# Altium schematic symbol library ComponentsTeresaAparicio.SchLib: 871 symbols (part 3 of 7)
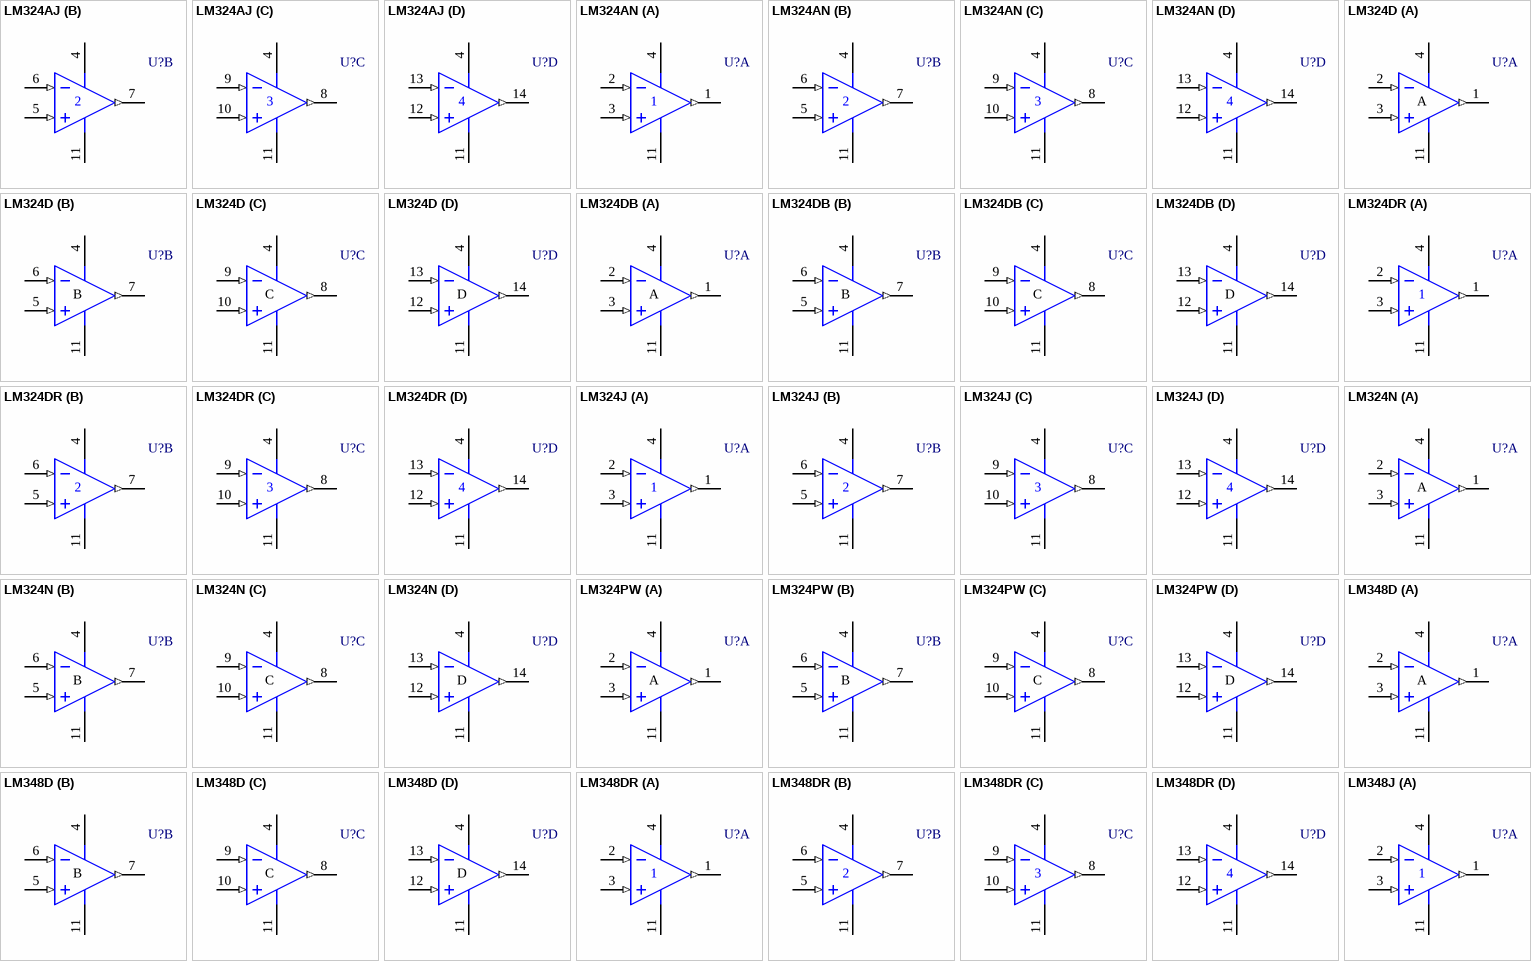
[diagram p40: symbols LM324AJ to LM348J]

## LM348DR
designator U?
Quadruple Operational Amplifier
footprint D014_N (SOIC, 14-Leads, Body 8.7x3.9mm, Pitch 1.27mm, IPC Medium Density)
footprint D014_L (SOIC, 14-Leads, Body 8.7x3.9mm, Pitch 1.27mm, IPC High Density)
footprint D014_M (SOIC, 14-Leads, Body 8.7x3.9mm, Pitch 1.27mm, IPC Low Density)
3D model D014 (14-Pin Small Outline Integrated Circuit 1.27 mm Pitch)
pins on every part: 4 V+ (power), 11 V- (power)
part A pins: 1 OUT (out), 2 IN- (in), 3 IN+ (in)
part B pins: 5 IN+ (in), 6 IN- (in), 7 OUT (out)
part C pins: 8 OUT (out), 9 IN- (in), 10 IN+ (in)
part D pins: 12 IN+ (in), 13 IN- (in), 14 OUT (out)

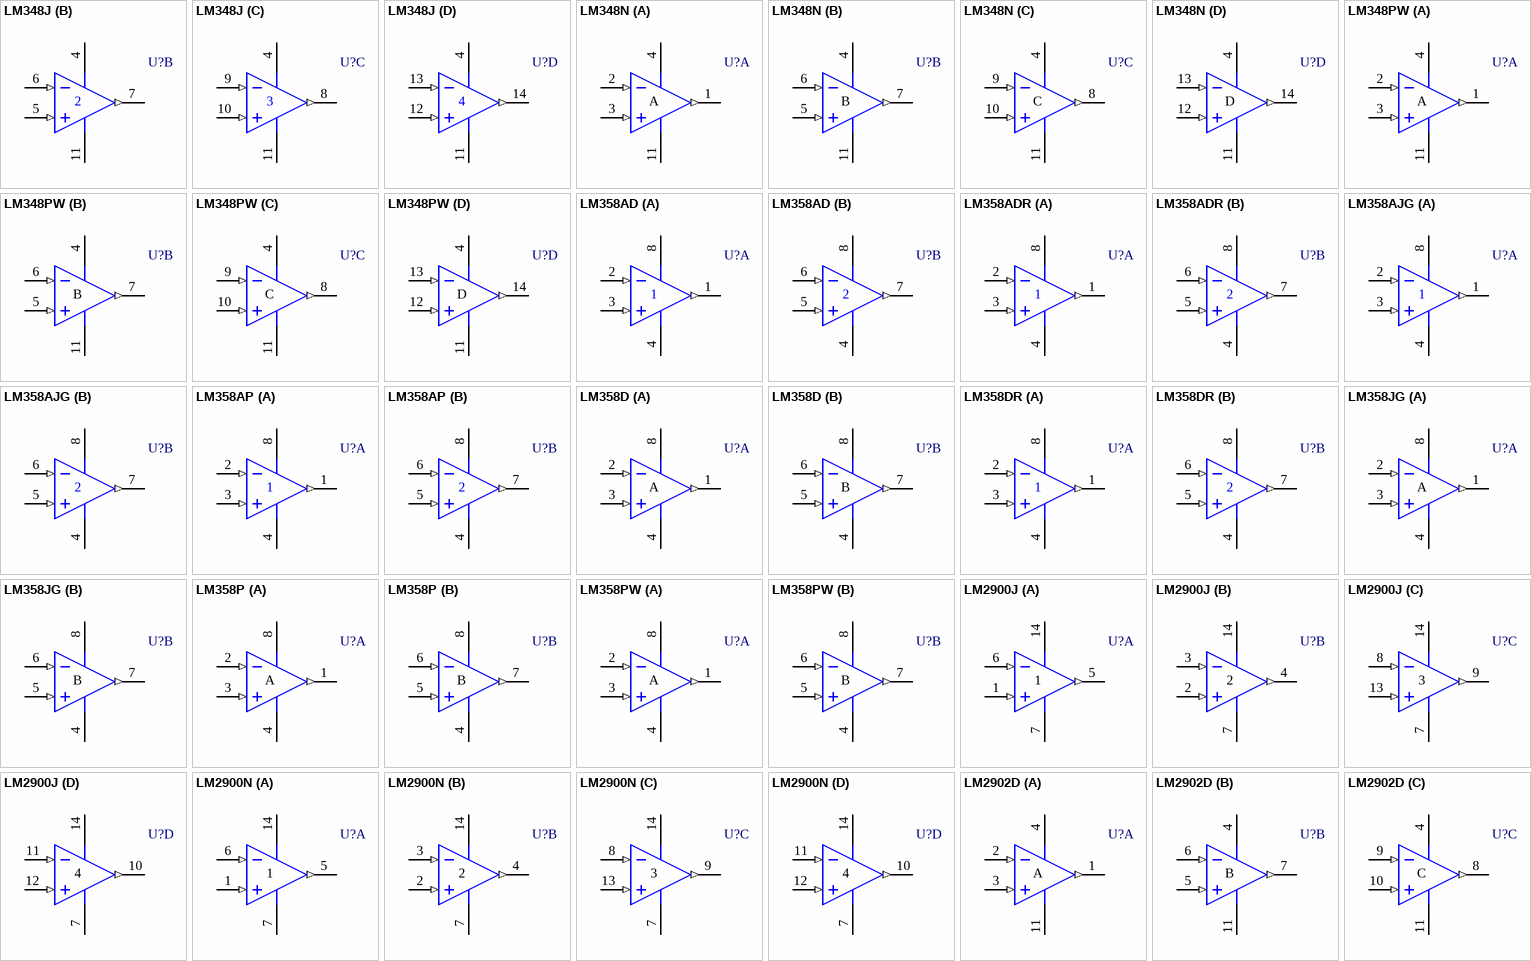
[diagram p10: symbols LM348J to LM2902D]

## LM348J
designator U?
Quadruple Operational Amplifier
footprint J014 (DIP; 14 Leads; Row Spacing 7.62 mm; Pitch 2.54 mm)
3D model J014 (DIP; 14 Leads; Row Spacing 7.62 mm; Pitch 2.54 mm)
pins on every part: 4 V+ (power), 11 V- (power)
part A pins: 1 OUT (out), 2 IN- (in), 3 IN+ (in)
part B pins: 5 IN+ (in), 6 IN- (in), 7 OUT (out)
part C pins: 8 OUT (out), 9 IN- (in), 10 IN+ (in)
part D pins: 12 IN+ (in), 13 IN- (in), 14 OUT (out)

## LM348N
designator U?
Quadruple Operational Amplifier
footprint N014 (DIP; 14 Leads; Row Spacing 7.62 mm; Pitch 2.54 mm)
3D model N014 (DIP; 14 Leads; Row Spacing 7.62 mm; Pitch 2.54 mm)
simulation model LM348 (SUBCKT)
pins on every part: 4 V+ (power), 11 V- (power)
part A pins: 1 OUT (out), 2 IN- (in), 3 IN+ (in)
part B pins: 5 IN+ (in), 6 IN- (in), 7 OUT (out)
part C pins: 8 OUT (out), 9 IN- (in), 10 IN+ (in)
part D pins: 12 IN+ (in), 13 IN- (in), 14 OUT (out)

## LM348PW
designator U?
Quadruple Operational Amplifier
footprint PW014_N (TSOP, 14-Leads, Body 5x4.4mm, Pitch 0.65mm, IPC Medium Density)
footprint PW014_L (TSOP, 14-Leads, Body 5x4.4mm, Pitch 0.65mm, IPC High Density)
footprint PW014_M (TSOP, 14-Leads, Body 5x4.4mm, Pitch 0.65mm, IPC Low Density)
3D model PW014 (14-Pin Thin Small Outline Package 0.65 mm Pitch)
simulation model LM348 (SUBCKT)
pins on every part: 4 V+ (power), 11 V- (power)
part A pins: 1 OUT (out), 2 IN- (in), 3 IN+ (in)
part B pins: 5 IN+ (in), 6 IN- (in), 7 OUT (out)
part C pins: 8 OUT (out), 9 IN- (in), 10 IN+ (in)
part D pins: 12 IN+ (in), 13 IN- (in), 14 OUT (out)

## LM358AD
designator U?
Dual Operational Amplifier
footprint D008_L (SOIC, 8-Leads, Body 4.9x3.9mm, Pitch 1.27mm, IPC High Density)
footprint D008_M (SOIC, 8-Leads, Body 4.9x3.9mm, Pitch 1.27mm, IPC Low Density)
footprint D008_M (SOIC, 8-Leads, Body 4.9x3.9mm, Pitch 1.27mm, IPC Low Density)
3D model D008 (8-Pin Small Outline Integrated Circuit 1.27 mm Pitch)
pins on every part: 4 V- (power), 8 V+ (power)
part A pins: 1 OUT (out), 2 IN- (in), 3 IN+ (in)
part B pins: 5 IN+ (in), 6 IN- (in), 7 OUT (out)

## LM358ADR
designator U?
Dual Operational Amplifier
footprint D008_L (SOIC, 8-Leads, Body 4.9x3.9mm, Pitch 1.27mm, IPC High Density)
footprint D008_M (SOIC, 8-Leads, Body 4.9x3.9mm, Pitch 1.27mm, IPC Low Density)
footprint D008_M (SOIC, 8-Leads, Body 4.9x3.9mm, Pitch 1.27mm, IPC Low Density)
3D model D008 (8-Pin Small Outline Integrated Circuit 1.27 mm Pitch)
pins on every part: 4 V- (power), 8 V+ (power)
part A pins: 1 OUT (out), 2 IN- (in), 3 IN+ (in)
part B pins: 5 IN+ (in), 6 IN- (in), 7 OUT (out)

## LM358AJG
designator U?
Dual Operational Amplifier
footprint JG008 (DIP; 8 Leads; Row Spacing 7.62 mm; Pitch 2.54 mm)
3D model JG008 (DIP; 8 Leads; Row Spacing 7.62 mm; Pitch 2.54 mm)
pins on every part: 4 V- (power), 8 V+ (power)
part A pins: 1 OUT (out), 2 IN- (in), 3 IN+ (in)
part B pins: 5 IN+ (in), 6 IN- (in), 7 OUT (out)

## LM358AP
designator U?
Dual Operational Amplifier
footprint P008 (DIP; 8 Leads; Row Spacing 7.62 mm; Pitch 2.54 mm)
3D model P008 (PCB3D Model)
pins on every part: 4 V- (power), 8 V+ (power)
part A pins: 1 OUT (out), 2 IN- (in), 3 IN+ (in)
part B pins: 5 IN+ (in), 6 IN- (in), 7 OUT (out)

## LM358D
designator U?
Dual Operational Amplifier
footprint D008_L (SOIC, 8-Leads, Body 4.9x3.9mm, Pitch 1.27mm, IPC High Density)
footprint D008_M (SOIC, 8-Leads, Body 4.9x3.9mm, Pitch 1.27mm, IPC Low Density)
footprint D008_M (SOIC, 8-Leads, Body 4.9x3.9mm, Pitch 1.27mm, IPC Low Density)
3D model D008 (8-Pin Small Outline Integrated Circuit 1.27 mm Pitch)
simulation model LM358 (SUBCKT)
pins on every part: 4 V- (power), 8 V+ (power)
part A pins: 1 OUT (out), 2 IN- (in), 3 IN+ (in)
part B pins: 5 IN+ (in), 6 IN- (in), 7 OUT (out)

## LM358DR
designator U?
Dual Operational Amplifier
footprint D008_L (SOIC, 8-Leads, Body 4.9x3.9mm, Pitch 1.27mm, IPC High Density)
footprint D008_M (SOIC, 8-Leads, Body 4.9x3.9mm, Pitch 1.27mm, IPC Low Density)
footprint D008_M (SOIC, 8-Leads, Body 4.9x3.9mm, Pitch 1.27mm, IPC Low Density)
3D model D008 (8-Pin Small Outline Integrated Circuit 1.27 mm Pitch)
pins on every part: 4 V- (power), 8 V+ (power)
part A pins: 1 OUT (out), 2 IN- (in), 3 IN+ (in)
part B pins: 5 IN+ (in), 6 IN- (in), 7 OUT (out)

## LM358JG
designator U?
Dual Operational Amplifier
footprint JG008 (DIP; 8 Leads; Row Spacing 7.62 mm; Pitch 2.54 mm)
3D model JG008 (DIP; 8 Leads; Row Spacing 7.62 mm; Pitch 2.54 mm)
simulation model LM358 (SUBCKT)
pins on every part: 4 V- (power), 8 V+ (power)
part A pins: 1 OUT (out), 2 IN- (in), 3 IN+ (in)
part B pins: 5 IN+ (in), 6 IN- (in), 7 OUT (out)

## LM358P
designator U?
Dual Operational Amplifier
footprint P008 (DIP; 8 Leads; Row Spacing 7.62 mm; Pitch 2.54 mm)
3D model P008 (DIP; 8 Leads; Row Spacing 7.62 mm; Pitch 2.54 mm)
simulation model LM358 (SUBCKT)
pins on every part: 4 V- (power), 8 V+ (power)
part A pins: 1 OUT (out), 2 IN- (in), 3 IN+ (in)
part B pins: 5 IN+ (in), 6 IN- (in), 7 OUT (out)

## LM358PW
designator U?
Dual Operational Amplifier
footprint PW008_N (SOP, 8-Leads, Body 3x4.4mm, Pitch 0.65mm, IPC Medium Density)
footprint PW008_L (SOP, 8-Leads, Body 3x4.4mm, Pitch 0.65mm, IPC High Density)
footprint PW008_M (SOP, 8-Leads, Body 3x4.4mm, Pitch 0.65mm, IPC Low Density)
3D model PW008 (8-Pin Small Outline Package 0.65 mm Pitch)
simulation model LM358 (SUBCKT)
pins on every part: 4 V- (power), 8 V+ (power)
part A pins: 1 OUT (out), 2 IN- (in), 3 IN+ (in)
part B pins: 5 IN+ (in), 6 IN- (in), 7 OUT (out)

## LM2900J
designator U?
Quadruple Operational Amplifier
footprint J014 (DIP; 14 Leads; Row Spacing 7.62 mm; Pitch 2.54 mm)
3D model J014 (DIP; 14 Leads; Row Spacing 7.62 mm; Pitch 2.54 mm)
pins on every part: 7 GND (power), 14 V+ (power)
part A pins: 1 IN+ (in), 5 OUT (out), 6 IN- (in)
part B pins: 2 IN+ (in), 3 IN- (in), 4 OUT (out)
part C pins: 8 IN- (in), 9 OUT (out), 13 IN+ (in)
part D pins: 10 OUT (out), 11 IN- (in), 12 IN+ (in)

## LM2900N
designator U?
Quadruple Operational Amplifier
footprint N014 (DIP; 14 Leads; Row Spacing 7.62 mm; Pitch 2.54 mm)
3D model N014 (DIP; 14 Leads; Row Spacing 7.62 mm; Pitch 2.54 mm)
pins on every part: 7 GND (power), 14 V+ (power)
part A pins: 1 IN+ (in), 5 OUT (out), 6 IN- (in)
part B pins: 2 IN+ (in), 3 IN- (in), 4 OUT (out)
part C pins: 8 IN- (in), 9 OUT (out), 13 IN+ (in)
part D pins: 10 OUT (out), 11 IN- (in), 12 IN+ (in)

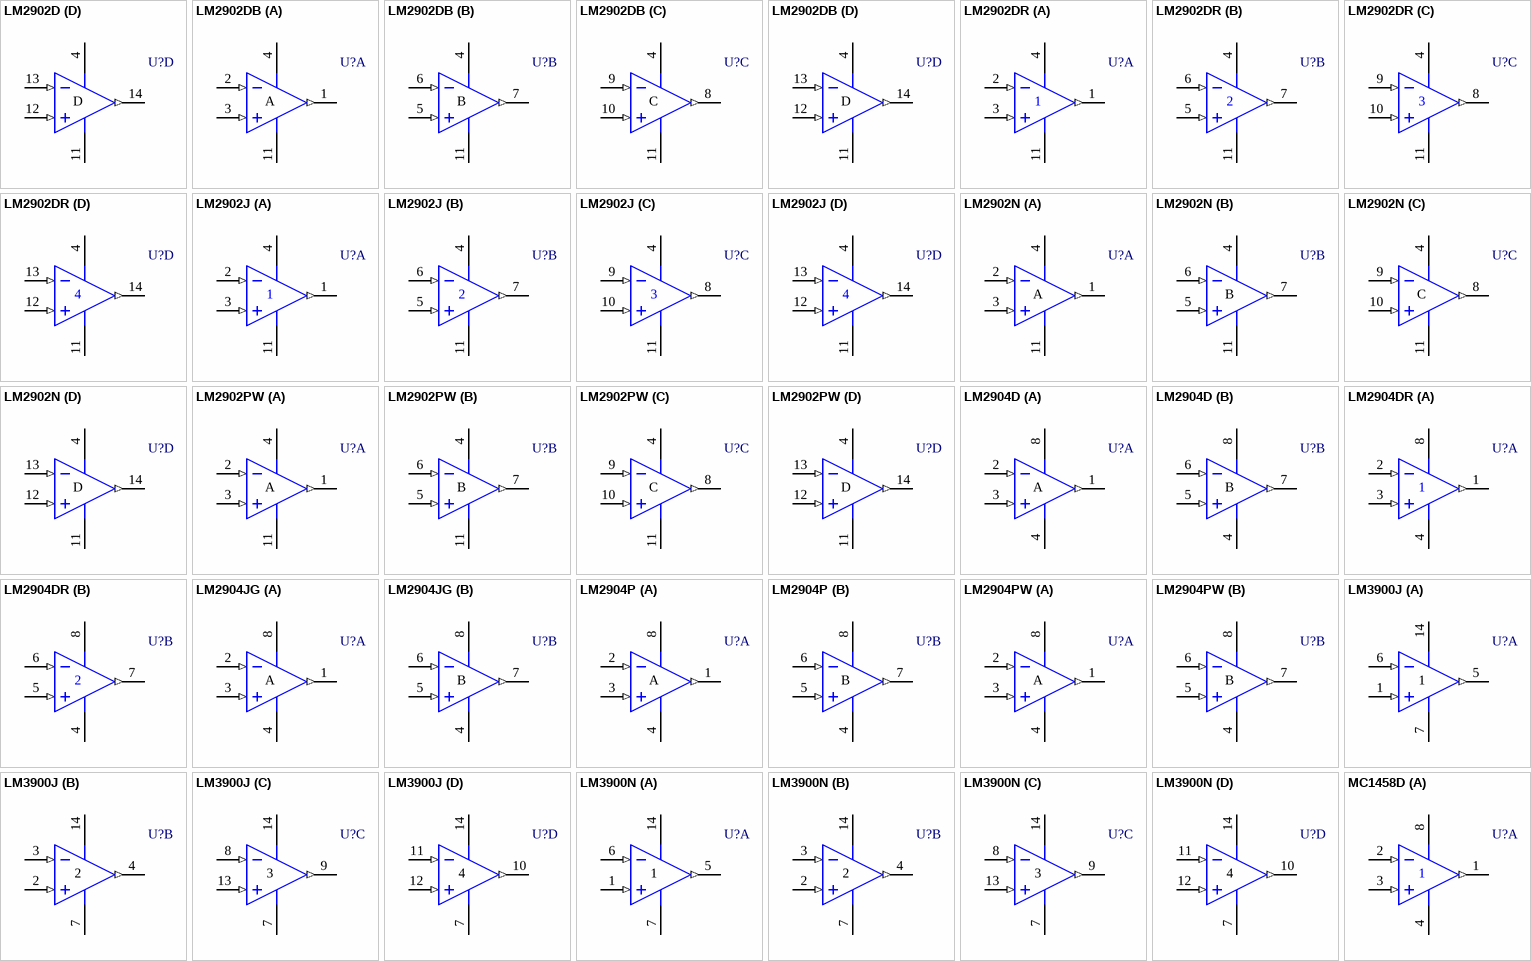
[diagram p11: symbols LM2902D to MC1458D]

## LM2902D
designator U?
Quadruple Operational Amplifier
footprint D014_N (SOIC, 14-Leads, Body 8.7x3.9mm, Pitch 1.27mm, IPC Medium Density)
footprint D014_L (SOIC, 14-Leads, Body 8.7x3.9mm, Pitch 1.27mm, IPC High Density)
footprint D014_M (SOIC, 14-Leads, Body 8.7x3.9mm, Pitch 1.27mm, IPC Low Density)
3D model D014 (14-Pin Small Outline Integrated Circuit 1.27 mm Pitch)
simulation model LM2902 (SUBCKT)
pins on every part: 4 V+ (power), 11 V- (power)
part A pins: 1 OUT (out), 2 IN- (in), 3 IN+ (in)
part B pins: 5 IN+ (in), 6 IN- (in), 7 OUT (out)
part C pins: 8 OUT (out), 9 IN- (in), 10 IN+ (in)
part D pins: 12 IN+ (in), 13 IN- (in), 14 OUT (out)

## LM2902DB
designator U?
Quadruple Operational Amplifier
footprint DB014_N (SOP, 14-Leads, Body 6.2x5.3mm, Pitch 0.65mm, IPC Medium Density)
footprint DB014_L (SOP, 14-Leads, Body 6.2x5.3mm, Pitch 0.65mm, IPC High Density)
footprint DB014_M (SOP, 14-Leads, Body 6.2x5.3mm, Pitch 0.65mm, IPC Low Density)
3D model DB014 (14-Pin Plastic Small Outline Package 0.65 mm Pitch)
simulation model LM2902 (SUBCKT)
pins on every part: 4 V+ (power), 11 V- (power)
part A pins: 1 OUT (out), 2 IN- (in), 3 IN+ (in)
part B pins: 5 IN+ (in), 6 IN- (in), 7 OUT (out)
part C pins: 8 OUT (out), 9 IN- (in), 10 IN+ (in)
part D pins: 12 IN+ (in), 13 IN- (in), 14 OUT (out)

## LM2902DR
designator U?
Quadruple Operational Amplifier
footprint D014_N (SOIC, 14-Leads, Body 8.7x3.9mm, Pitch 1.27mm, IPC Medium Density)
footprint D014_L (SOIC, 14-Leads, Body 8.7x3.9mm, Pitch 1.27mm, IPC High Density)
footprint D014_M (SOIC, 14-Leads, Body 8.7x3.9mm, Pitch 1.27mm, IPC Low Density)
3D model D014 (14-Pin Small Outline Integrated Circuit 1.27 mm Pitch)
pins on every part: 4 V+ (power), 11 V- (power)
part A pins: 1 OUT (out), 2 IN- (in), 3 IN+ (in)
part B pins: 5 IN+ (in), 6 IN- (in), 7 OUT (out)
part C pins: 8 OUT (out), 9 IN- (in), 10 IN+ (in)
part D pins: 12 IN+ (in), 13 IN- (in), 14 OUT (out)

## LM2902J
designator U?
Quadruple Operational Amplifier
footprint J014 (DIP; 14 Leads; Row Spacing 7.62 mm; Pitch 2.54 mm)
3D model J014 (DIP; 14 Leads; Row Spacing 7.62 mm; Pitch 2.54 mm)
pins on every part: 4 V+ (power), 11 V- (power)
part A pins: 1 OUT (out), 2 IN- (in), 3 IN+ (in)
part B pins: 5 IN+ (in), 6 IN- (in), 7 OUT (out)
part C pins: 8 OUT (out), 9 IN- (in), 10 IN+ (in)
part D pins: 12 IN+ (in), 13 IN- (in), 14 OUT (out)

## LM2902N
designator U?
Quadruple Operational Amplifier
footprint N014 (DIP; 14 Leads; Row Spacing 7.62 mm; Pitch 2.54 mm)
3D model N014 (DIP; 14 Leads; Row Spacing 7.62 mm; Pitch 2.54 mm)
simulation model LM2902 (SUBCKT)
pins on every part: 4 V+ (power), 11 V- (power)
part A pins: 1 OUT (out), 2 IN- (in), 3 IN+ (in)
part B pins: 5 IN+ (in), 6 IN- (in), 7 OUT (out)
part C pins: 8 OUT (out), 9 IN- (in), 10 IN+ (in)
part D pins: 12 IN+ (in), 13 IN- (in), 14 OUT (out)

## LM2902PW
designator U?
Quadruple Operational Amplifier
footprint PW014_N (TSOP, 14-Leads, Body 5x4.4mm, Pitch 0.65mm, IPC Medium Density)
footprint PW014_L (TSOP, 14-Leads, Body 5x4.4mm, Pitch 0.65mm, IPC High Density)
footprint PW014_M (TSOP, 14-Leads, Body 5x4.4mm, Pitch 0.65mm, IPC Low Density)
3D model PW014 (14-Pin Thin Small Outline Package 0.65 mm Pitch)
simulation model LM2902 (SUBCKT)
pins on every part: 4 V+ (power), 11 V- (power)
part A pins: 1 OUT (out), 2 IN- (in), 3 IN+ (in)
part B pins: 5 IN+ (in), 6 IN- (in), 7 OUT (out)
part C pins: 8 OUT (out), 9 IN- (in), 10 IN+ (in)
part D pins: 12 IN+ (in), 13 IN- (in), 14 OUT (out)

## LM2904D
designator U?
Dual Operational Amplifier
footprint D008_L (SOIC, 8-Leads, Body 4.9x3.9mm, Pitch 1.27mm, IPC High Density)
footprint D008_M (SOIC, 8-Leads, Body 4.9x3.9mm, Pitch 1.27mm, IPC Low Density)
footprint D008_M (SOIC, 8-Leads, Body 4.9x3.9mm, Pitch 1.27mm, IPC Low Density)
3D model D008 (8-Pin Small Outline Integrated Circuit 1.27 mm Pitch)
simulation model LM2904 (SUBCKT)
pins on every part: 4 V- (power), 8 V+ (power)
part A pins: 1 OUT (out), 2 IN- (in), 3 IN+ (in)
part B pins: 5 IN+ (in), 6 IN- (in), 7 OUT (out)

## LM2904DR
designator U?
Dual Operational Amplifier
footprint D008_L (SOIC, 8-Leads, Body 4.9x3.9mm, Pitch 1.27mm, IPC High Density)
footprint D008_M (SOIC, 8-Leads, Body 4.9x3.9mm, Pitch 1.27mm, IPC Low Density)
footprint D008_M (SOIC, 8-Leads, Body 4.9x3.9mm, Pitch 1.27mm, IPC Low Density)
3D model D008 (8-Pin Small Outline Integrated Circuit 1.27 mm Pitch)
pins on every part: 4 V- (power), 8 V+ (power)
part A pins: 1 OUT (out), 2 IN- (in), 3 IN+ (in)
part B pins: 5 IN+ (in), 6 IN- (in), 7 OUT (out)

## LM2904JG
designator U?
Dual Operational Amplifier
footprint JG008 (DIP; 8 Leads; Row Spacing 7.62 mm; Pitch 2.54 mm)
3D model JG008 (DIP; 8 Leads; Row Spacing 7.62 mm; Pitch 2.54 mm)
simulation model LM2904 (SUBCKT)
pins on every part: 4 V- (power), 8 V+ (power)
part A pins: 1 OUT (out), 2 IN- (in), 3 IN+ (in)
part B pins: 5 IN+ (in), 6 IN- (in), 7 OUT (out)

## LM2904P
designator U?
Dual Operational Amplifier
footprint P008 (DIP; 8 Leads; Row Spacing 7.62 mm; Pitch 2.54 mm)
3D model P008 (DIP; 8 Leads; Row Spacing 7.62 mm; Pitch 2.54 mm)
simulation model LM2904 (SUBCKT)
pins on every part: 4 V- (power), 8 V+ (power)
part A pins: 1 OUT (out), 2 IN- (in), 3 IN+ (in)
part B pins: 5 IN+ (in), 6 IN- (in), 7 OUT (out)

## LM2904PW
designator U?
Dual Operational Amplifier
footprint PW008_N (SOP, 8-Leads, Body 3x4.4mm, Pitch 0.65mm, IPC Medium Density)
footprint PW008_L (SOP, 8-Leads, Body 3x4.4mm, Pitch 0.65mm, IPC High Density)
footprint PW008_M (SOP, 8-Leads, Body 3x4.4mm, Pitch 0.65mm, IPC Low Density)
3D model PW008 (8-Pin Small Outline Package 0.65 mm Pitch)
simulation model LM2904 (SUBCKT)
pins on every part: 4 V- (power), 8 V+ (power)
part A pins: 1 OUT (out), 2 IN- (in), 3 IN+ (in)
part B pins: 5 IN+ (in), 6 IN- (in), 7 OUT (out)

## LM3900J
designator U?
Quadruple Operational Amplifier
footprint J014 (DIP; 14 Leads; Row Spacing 7.62 mm; Pitch 2.54 mm)
3D model J014 (DIP; 14 Leads; Row Spacing 7.62 mm; Pitch 2.54 mm)
pins on every part: 7 GND (power), 14 V+ (power)
part A pins: 1 IN+ (in), 5 OUT (out), 6 IN- (in)
part B pins: 2 IN+ (in), 3 IN- (in), 4 OUT (out)
part C pins: 8 IN- (in), 9 OUT (out), 13 IN+ (in)
part D pins: 10 OUT (out), 11 IN- (in), 12 IN+ (in)

## LM3900N
designator U?
Quadruple Operational Amplifier
footprint N014 (DIP; 14 Leads; Row Spacing 7.62 mm; Pitch 2.54 mm)
3D model N014 (DIP; 14 Leads; Row Spacing 7.62 mm; Pitch 2.54 mm)
pins on every part: 7 GND (power), 14 V+ (power)
part A pins: 1 IN+ (in), 5 OUT (out), 6 IN- (in)
part B pins: 2 IN+ (in), 3 IN- (in), 4 OUT (out)
part C pins: 8 IN- (in), 9 OUT (out), 13 IN+ (in)
part D pins: 10 OUT (out), 11 IN- (in), 12 IN+ (in)

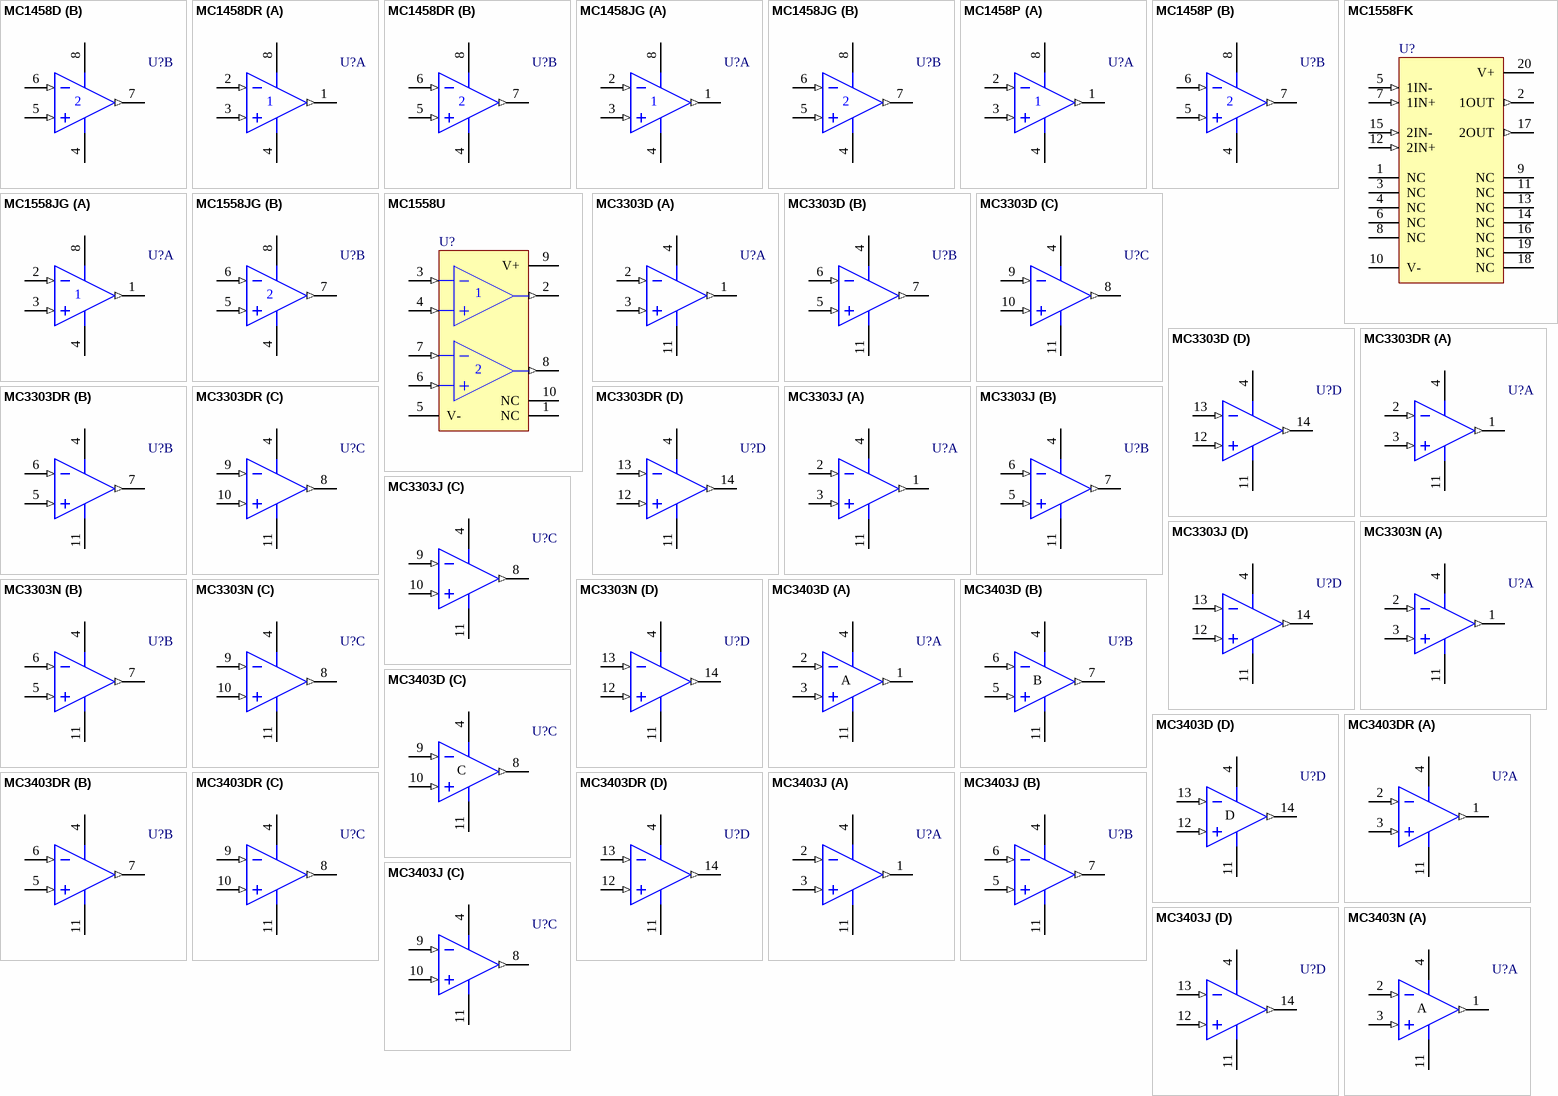
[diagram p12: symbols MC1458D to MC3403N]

## MC1458D
designator U?
Dual General-Purpose Operational Amplifier
footprint D008_L (SOIC, 8-Leads, Body 4.9x3.9mm, Pitch 1.27mm, IPC High Density)
footprint D008_M (SOIC, 8-Leads, Body 4.9x3.9mm, Pitch 1.27mm, IPC Low Density)
footprint D008_M (SOIC, 8-Leads, Body 4.9x3.9mm, Pitch 1.27mm, IPC Low Density)
3D model D008 (8-Pin Small Outline Integrated Circuit 1.27 mm Pitch)
pins on every part: 4 V- (power), 8 V+ (power)
part A pins: 1 OUT (out), 2 IN- (in), 3 IN+ (in)
part B pins: 5 IN+ (in), 6 IN- (in), 7 OUT (out)

## MC1458DR
designator U?
Dual General-Purpose Operational Amplifier
footprint D008_L (SOIC, 8-Leads, Body 4.9x3.9mm, Pitch 1.27mm, IPC High Density)
footprint D008_M (SOIC, 8-Leads, Body 4.9x3.9mm, Pitch 1.27mm, IPC Low Density)
footprint D008_M (SOIC, 8-Leads, Body 4.9x3.9mm, Pitch 1.27mm, IPC Low Density)
3D model D008 (8-Pin Small Outline Integrated Circuit 1.27 mm Pitch)
pins on every part: 4 V- (power), 8 V+ (power)
part A pins: 1 OUT (out), 2 IN- (in), 3 IN+ (in)
part B pins: 5 IN+ (in), 6 IN- (in), 7 OUT (out)

## MC1458JG
designator U?
Dual General-Purpose Operational Amplifier
footprint JG008 (DIP; 8 Leads; Row Spacing 7.62 mm; Pitch 2.54 mm)
3D model JG008 (DIP; 8 Leads; Row Spacing 7.62 mm; Pitch 2.54 mm)
pins on every part: 4 V- (power), 8 V+ (power)
part A pins: 1 OUT (out), 2 IN- (in), 3 IN+ (in)
part B pins: 5 IN+ (in), 6 IN- (in), 7 OUT (out)

## MC1458P
designator U?
Dual General-Purpose Operational Amplifier
footprint P008 (DIP; 8 Leads; Row Spacing 7.62 mm; Pitch 2.54 mm)
3D model P008 (DIP; 8 Leads; Row Spacing 7.62 mm; Pitch 2.54 mm)
pins on every part: 4 V- (power), 8 V+ (power)
part A pins: 1 OUT (out), 2 IN- (in), 3 IN+ (in)
part B pins: 5 IN+ (in), 6 IN- (in), 7 OUT (out)

## MC1558FK
designator U?
Dual General-Purpose Operational Amplifier
footprint FK020 (Leadless Chip Carrier; 20 Terminals; Body 8.9 x 8.9 mm)
pins: 1 NC, 2 1OUT (out), 3 NC, 4 NC, 5 1IN- (in), 6 NC, 7 1IN+ (in), 8 NC, 9 NC, 10 V- (power), 11 NC, 12 2IN+ (in), 13 NC, 14 NC, 15 2IN- (in), 16 NC, 17 2OUT (out), 18 NC, 19 NC, 20 V+ (power)

## MC1558JG
designator U?
Dual General-Purpose Operational Amplifier
footprint JG008 (DIP; 8 Leads; Row Spacing 7.62 mm; Pitch 2.54 mm)
3D model JG008 (DIP; 8 Leads; Row Spacing 7.62 mm; Pitch 2.54 mm)
pins on every part: 4 V- (power), 8 V+ (power)
part A pins: 1 OUT (out), 2 IN- (in), 3 IN+ (in)
part B pins: 5 IN+ (in), 6 IN- (in), 7 OUT (out)

## MC1558U
designator U?
Dual General-Purpose Operational Amplifier
footprint U010 (DFP; 10 Leads; Body 7.1 x 6.4 mm (LxW max); Pitch 1.27 mm)
3D model U010 (DFP; 10 Leads; Body 7.1 x 6.4 mm (LxW max); Pitch 1.27 mm)
pins: 1 NC, 2 OUT (out), 3 IN- (in), 4 IN+ (in), 5 V- (power), 6 IN+ (in), 7 IN- (in), 8 OUT (out), 9 V+ (power), 10 NC

## MC3303D
designator U?
Quadruple Low-Power Operational Amplifier
footprint D014_N (SOIC, 14-Leads, Body 8.7x3.9mm, Pitch 1.27mm, IPC Medium Density)
footprint D014_L (SOIC, 14-Leads, Body 8.7x3.9mm, Pitch 1.27mm, IPC High Density)
footprint D014_M (SOIC, 14-Leads, Body 8.7x3.9mm, Pitch 1.27mm, IPC Low Density)
3D model D014 (14-Pin Small Outline Integrated Circuit 1.27 mm Pitch)
pins on every part: 4 V+ (power), 11 V- (power)
part A pins: 1 OUT (out), 2 IN- (in), 3 IN+ (in)
part B pins: 5 IN+ (in), 6 IN- (in), 7 OUT (out)
part C pins: 8 OUT (out), 9 IN- (in), 10 IN+ (in)
part D pins: 12 IN+ (in), 13 IN- (in), 14 OUT (out)

## MC3303DR
designator U?
Quadruple Low-Power Operational Amplifier
footprint D014_N (SOIC, 14-Leads, Body 8.7x3.9mm, Pitch 1.27mm, IPC Medium Density)
footprint D014_L (SOIC, 14-Leads, Body 8.7x3.9mm, Pitch 1.27mm, IPC High Density)
footprint D014_M (SOIC, 14-Leads, Body 8.7x3.9mm, Pitch 1.27mm, IPC Low Density)
3D model D014 (14-Pin Small Outline Integrated Circuit 1.27 mm Pitch)
pins on every part: 4 V+ (power), 11 V- (power)
part A pins: 1 OUT (out), 2 IN- (in), 3 IN+ (in)
part B pins: 5 IN+ (in), 6 IN- (in), 7 OUT (out)
part C pins: 8 OUT (out), 9 IN- (in), 10 IN+ (in)
part D pins: 12 IN+ (in), 13 IN- (in), 14 OUT (out)

## MC3303J
designator U?
Quadruple Low-Power Operational Amplifier
footprint J014 (DIP; 14 Leads; Row Spacing 7.62 mm; Pitch 2.54 mm)
3D model J014 (DIP; 14 Leads; Row Spacing 7.62 mm; Pitch 2.54 mm)
pins on every part: 4 V+ (power), 11 V- (power)
part A pins: 1 OUT (out), 2 IN- (in), 3 IN+ (in)
part B pins: 5 IN+ (in), 6 IN- (in), 7 OUT (out)
part C pins: 8 OUT (out), 9 IN- (in), 10 IN+ (in)
part D pins: 12 IN+ (in), 13 IN- (in), 14 OUT (out)

## MC3303N
designator U?
Quadruple Low-Power Operational Amplifier
footprint N014 (DIP; 14 Leads; Row Spacing 7.62 mm; Pitch 2.54 mm)
3D model N014 (DIP; 14 Leads; Row Spacing 7.62 mm; Pitch 2.54 mm)
pins on every part: 4 V+ (power), 11 V- (power)
part A pins: 1 OUT (out), 2 IN- (in), 3 IN+ (in)
part B pins: 5 IN+ (in), 6 IN- (in), 7 OUT (out)
part C pins: 8 OUT (out), 9 IN- (in), 10 IN+ (in)
part D pins: 12 IN+ (in), 13 IN- (in), 14 OUT (out)

## MC3403D
designator U?
Quadruple Low-Power Operational Amplifier
footprint D014_N (SOIC, 14-Leads, Body 8.7x3.9mm, Pitch 1.27mm, IPC Medium Density)
footprint D014_L (SOIC, 14-Leads, Body 8.7x3.9mm, Pitch 1.27mm, IPC High Density)
footprint D014_M (SOIC, 14-Leads, Body 8.7x3.9mm, Pitch 1.27mm, IPC Low Density)
3D model D014 (14-Pin Small Outline Integrated Circuit 1.27 mm Pitch)
simulation model MC3403 (SUBCKT)
pins on every part: 4 V+ (power), 11 V- (power)
part A pins: 1 OUT (out), 2 IN- (in), 3 IN+ (in)
part B pins: 5 IN+ (in), 6 IN- (in), 7 OUT (out)
part C pins: 8 OUT (out), 9 IN- (in), 10 IN+ (in)
part D pins: 12 IN+ (in), 13 IN- (in), 14 OUT (out)

## MC3403DR
designator U?
Quadruple Low-Power Operational Amplifier
footprint D014_N (SOIC, 14-Leads, Body 8.7x3.9mm, Pitch 1.27mm, IPC Medium Density)
footprint D014_L (SOIC, 14-Leads, Body 8.7x3.9mm, Pitch 1.27mm, IPC High Density)
footprint D014_M (SOIC, 14-Leads, Body 8.7x3.9mm, Pitch 1.27mm, IPC Low Density)
3D model D014 (14-Pin Small Outline Integrated Circuit 1.27 mm Pitch)
pins on every part: 4 V+ (power), 11 V- (power)
part A pins: 1 OUT (out), 2 IN- (in), 3 IN+ (in)
part B pins: 5 IN+ (in), 6 IN- (in), 7 OUT (out)
part C pins: 8 OUT (out), 9 IN- (in), 10 IN+ (in)
part D pins: 12 IN+ (in), 13 IN- (in), 14 OUT (out)

## MC3403J
designator U?
Quadruple Low-Power Operational Amplifier
footprint J014 (DIP; 14 Leads; Row Spacing 7.62 mm; Pitch 2.54 mm)
3D model J014 (DIP; 14 Leads; Row Spacing 7.62 mm; Pitch 2.54 mm)
pins on every part: 4 V+ (power), 11 V- (power)
part A pins: 1 OUT (out), 2 IN- (in), 3 IN+ (in)
part B pins: 5 IN+ (in), 6 IN- (in), 7 OUT (out)
part C pins: 8 OUT (out), 9 IN- (in), 10 IN+ (in)
part D pins: 12 IN+ (in), 13 IN- (in), 14 OUT (out)

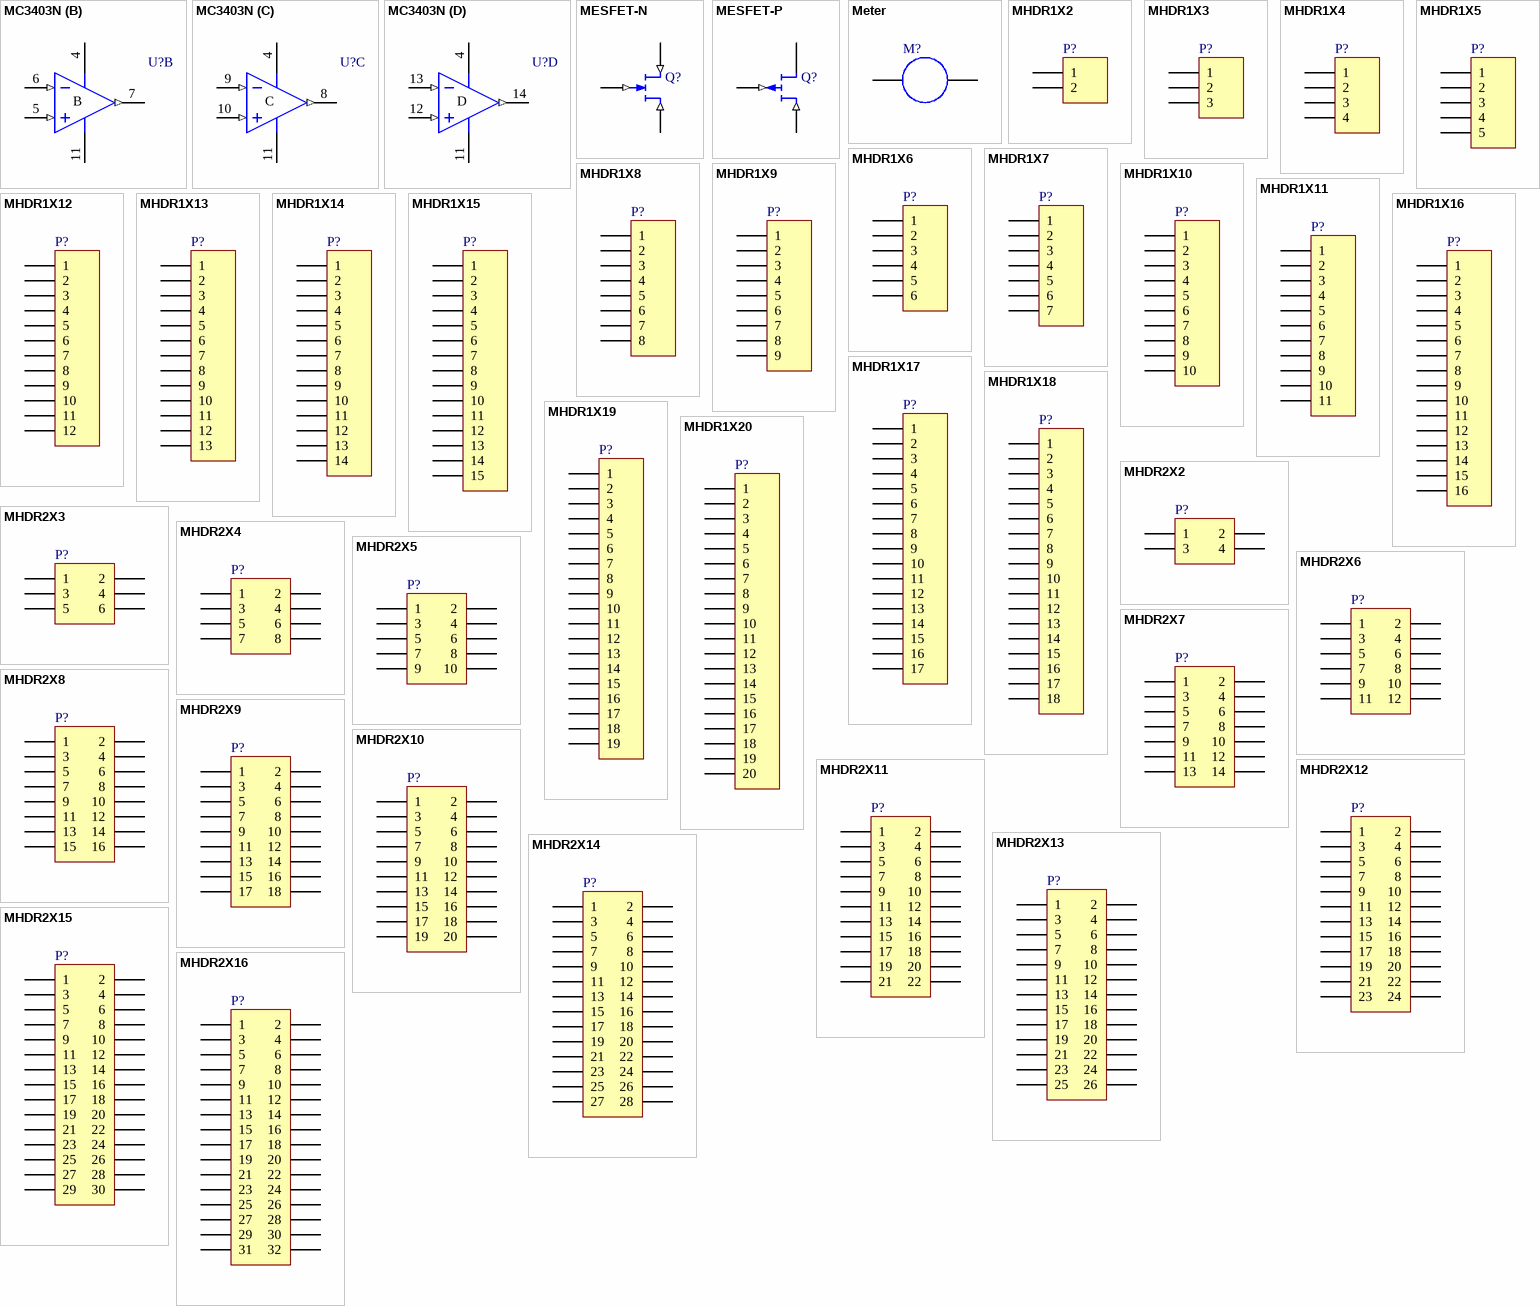
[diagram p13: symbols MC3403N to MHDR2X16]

## MC3403N
designator U?
Quadruple Low-Power Operational Amplifier
footprint N014 (DIP; 14 Leads; Row Spacing 7.62 mm; Pitch 2.54 mm)
3D model N014 (DIP; 14 Leads; Row Spacing 7.62 mm; Pitch 2.54 mm)
simulation model MC3403 (SUBCKT)
pins on every part: 4 V+ (power), 11 V- (power)
part A pins: 1 OUT (out), 2 IN- (in), 3 IN+ (in)
part B pins: 5 IN+ (in), 6 IN- (in), 7 OUT (out)
part C pins: 8 OUT (out), 9 IN- (in), 10 IN+ (in)
part D pins: 12 IN+ (in), 13 IN- (in), 14 OUT (out)

## MESFET-N
designator Q?
N-Channel MESFET
footprint TO-18 (Can; 3 Leads; Pin Circle Dia. 2.54 mm; Lead Dia. 0.48 mm (max))
simulation model NMESFET (MESFET-N)
pins: 1 D (in), 2 G (in), 3 S (in)

## MESFET-P
designator Q?
P-Channel MESFET
footprint TO-18 (Can; 3 Leads; Pin Circle Dia. 2.54 mm; Lead Dia. 0.48 mm (max))
simulation model PMESFET (MESFET-P)
pins: 1 D (in), 2 G (in), 3 S

## Meter
designator M?
Indicating Instrument; Note: Place a "letter" into the symbol to show the function of the meter or instrument
footprint RAD-0.1 (Radial Cap, Thru-Hole; 2 Leads; 0.1 in Pin Spacing)
pins: 1, 2

## MHDR1X2
designator P?
Header, 2-Pin
footprint MHDR1X2 (Connector; Header; 2 Position)
signal-integrity model Connector
pins: 1, 2

## MHDR1X3
designator P?
Header, 3-Pin
footprint MHDR1X3 (Connector; Header; 3 Position)
signal-integrity model Connector
pins: 1, 2, 3

## MHDR1X4
designator P?
Header, 4-Pin
footprint MHDR1X4 (Connector; Header; 4 Position)
signal-integrity model Connector
pins: 1, 2, 3, 4

## MHDR1X5
designator P?
Header, 5-Pin
footprint MHDR1X5 (Connector; Header; 5 Position)
signal-integrity model Connector
pins: 1, 2, 3, 4, 5

## MHDR1X6
designator P?
Header, 6-Pin
footprint MHDR1X6 (Connector; Header; 6 Position)
signal-integrity model Connector
pins: 1, 2, 3, 4, 5, 6

## MHDR1X7
designator P?
Header, 7-Pin
footprint MHDR1X7 (Connector; Header; 7 Position)
signal-integrity model Connector
pins: 1, 2, 3, 4, 5, 6, 7

## MHDR1X8
designator P?
Header, 8-Pin
footprint MHDR1X8 (Connector; Header; 8 Position)
signal-integrity model Connector
pins: 1, 2, 3, 4, 5, 6, 7, 8

## MHDR1X9
designator P?
Header, 9-Pin
footprint MHDR1X9 (Connector; Header; 9 Position)
signal-integrity model Connector
pins: 1, 2, 3, 4, 5, 6, 7, 8, 9

## MHDR1X10
designator P?
Header, 10-Pin
footprint MHDR1X10 (Connector; Header; 10 Position)
signal-integrity model Connector
pins: 1, 2, 3, 4, 5, 6, 7, 8, 9, 10

## MHDR1X11
designator P?
Header, 11-Pin
footprint MHDR1X11 (Connector; Header; 11 Position)
signal-integrity model Connector
pins: 1, 2, 3, 4, 5, 6, 7, 8, 9, 10, 11

## MHDR1X12
designator P?
Header, 12-Pin
footprint MHDR1X12 (Connector; Header; 12 Position)
signal-integrity model Connector
pins: 1, 2, 3, 4, 5, 6, 7, 8, 9, 10, 11, 12

## MHDR1X13
designator P?
Header, 13-Pin
footprint MHDR1X13 (Connector; Header; 13 Position)
signal-integrity model Connector
pins: 1, 2, 3, 4, 5, 6, 7, 8, 9, 10, 11, 12, 13

## MHDR1X14
designator P?
Header, 14-Pin
footprint MHDR1X14 (Connector; Header; 14 Position)
signal-integrity model Connector
pins: 1, 2, 3, 4, 5, 6, 7, 8, 9, 10, 11, 12, 13, 14

## MHDR1X15
designator P?
Header, 15-Pin
footprint MHDR1X15 (Connector; Header; 15 Position)
signal-integrity model Connector
pins: 1, 2, 3, 4, 5, 6, 7, 8, 9, 10, 11, 12, 13, 14, 15

## MHDR1X16
designator P?
Header, 16-Pin
footprint MHDR1X16 (Connector; Header; 16 Position)
signal-integrity model Connector
pins: 1, 2, 3, 4, 5, 6, 7, 8, 9, 10, 11, 12, 13, 14, 15, 16

## MHDR1X17
designator P?
Header, 17-Pin
footprint MHDR1X17 (Connector; Header; 17 Position)
signal-integrity model Connector
pins: 1, 2, 3, 4, 5, 6, 7, 8, 9, 10, 11, 12, 13, 14, 15, 16, 17

## MHDR1X18
designator P?
Header, 18-Pin
footprint MHDR1X18 (Connector; Header; 18 Position)
signal-integrity model Connector
pins: 1, 2, 3, 4, 5, 6, 7, 8, 9, 10, 11, 12, 13, 14, 15, 16, 17, 18

## MHDR1X19
designator P?
Header, 19-Pin
footprint MHDR1X19 (Connector; Header; 19 Position)
signal-integrity model Connector
pins: 1, 2, 3, 4, 5, 6, 7, 8, 9, 10, 11, 12, 13, 14, 15, 16, 17, 18, 19

## MHDR1X20
designator P?
Header, 20-Pin
footprint MHDR1X20 (Connector; Header; 20 Position)
signal-integrity model Connector
pins: 1, 2, 3, 4, 5, 6, 7, 8, 9, 10, 11, 12, 13, 14, 15, 16, 17, 18, 19, 20

## MHDR2X2
designator P?
Header, 2-Pin, Dual row
footprint MHDR2X2 (Connector; Header; 2x2 Position)
signal-integrity model Connector
pins: 1, 2, 3, 4

## MHDR2X3
designator P?
Header, 3-Pin, Dual row
footprint MHDR2X3 (Connector; Header; 3x2 Position)
signal-integrity model Connector
pins: 1, 2, 3, 4, 5, 6

## MHDR2X4
designator P?
Header, 4-Pin, Dual row
footprint MHDR2X4 (Connector; Header; 4x2 Position)
signal-integrity model Connector
pins: 1, 2, 3, 4, 5, 6, 7, 8

## MHDR2X5
designator P?
Header, 5-Pin, Dual row
footprint MHDR2X5 (Connector; Header; 5x2 Position)
signal-integrity model Connector
pins: 1, 2, 3, 4, 5, 6, 7, 8, 9, 10

## MHDR2X6
designator P?
Header, 6-Pin, Dual row
footprint MHDR2X6 (Connector; Header; 6x2 Position)
signal-integrity model Connector
pins: 1, 2, 3, 4, 5, 6, 7, 8, 9, 10, 11, 12

## MHDR2X7
designator P?
Header, 7-Pin, Dual row
footprint MHDR2X7 (Connector; Header; 7x2 Position)
signal-integrity model Connector
pins: 1, 2, 3, 4, 5, 6, 7, 8, 9, 10, 11, 12, 13, 14

## MHDR2X8
designator P?
Header, 8-Pin, Dual row
footprint MHDR2X8 (Connector; Header; 8x2 Position)
signal-integrity model Connector
pins: 1, 2, 3, 4, 5, 6, 7, 8, 9, 10, 11, 12, 13, 14, 15, 16

## MHDR2X9
designator P?
Header, 9-Pin, Dual row
footprint MHDR2X9 (Connector; Header; 9x2 Position)
signal-integrity model Connector
pins: 1, 2, 3, 4, 5, 6, 7, 8, 9, 10, 11, 12, 13, 14, 15, 16, 17, 18

## MHDR2X10
designator P?
Header, 10-Pin, Dual row
footprint MHDR2X10 (Connector; Header; 10x2 Position)
signal-integrity model Connector
pins: 1, 2, 3, 4, 5, 6, 7, 8, 9, 10, 11, 12, 13, 14, 15, 16, 17, 18, 19, 20

## MHDR2X11
designator P?
Header, 11-Pin, Dual row
footprint MHDR2X11 (Connector; Header; 11x2 Position)
signal-integrity model Connector
pins: 1, 2, 3, 4, 5, 6, 7, 8, 9, 10, 11, 12, 13, 14, 15, 16, 17, 18, 19, 20, 21, 22

## MHDR2X12
designator P?
Header, 12-Pin, Dual row
footprint MHDR2X12 (Connector; Header; 12x2 Position)
signal-integrity model Connector
pins: 1, 2, 3, 4, 5, 6, 7, 8, 9, 10, 11, 12, 13, 14, 15, 16, 17, 18, 19, 20, 21, 22, 23, 24

## MHDR2X13
designator P?
Header, 13-Pin, Dual row
footprint MHDR2X13 (Connector; Header; 13x2 Position)
signal-integrity model Connector
pins: 1, 2, 3, 4, 5, 6, 7, 8, 9, 10, 11, 12, 13, 14, 15, 16, 17, 18, 19, 20, 21, 22, 23, 24, 25, 26

## MHDR2X14
designator P?
Header, 14-Pin, Dual row
footprint MHDR2X14 (Connector; Header; 14x2 Position)
signal-integrity model Connector
pins: 1, 2, 3, 4, 5, 6, 7, 8, 9, 10, 11, 12, 13, 14, 15, 16, 17, 18, 19, 20, 21, 22, 23, 24, 25, 26, 27, 28

## MHDR2X15
designator P?
Header, 15-Pin, Dual row
footprint MHDR2X15 (Connector; Header; 15x2 Position)
signal-integrity model Connector
pins: 1, 2, 3, 4, 5, 6, 7, 8, 9, 10, 11, 12, 13, 14, 15, 16, 17, 18, 19, 20, 21, 22, 23, 24, 25, 26, 27, 28, 29, 30

## MHDR2X16
designator P?
Header, 16-Pin, Dual row
footprint MHDR2X16 (Connector; Header; 16x2 Position)
signal-integrity model Connector
pins: 1, 2, 3, 4, 5, 6, 7, 8, 9, 10, 11, 12, 13, 14, 15, 16, 17, 18, 19, 20, 21, 22, 23, 24, 25, 26, 27, 28, 29, 30, 31, 32

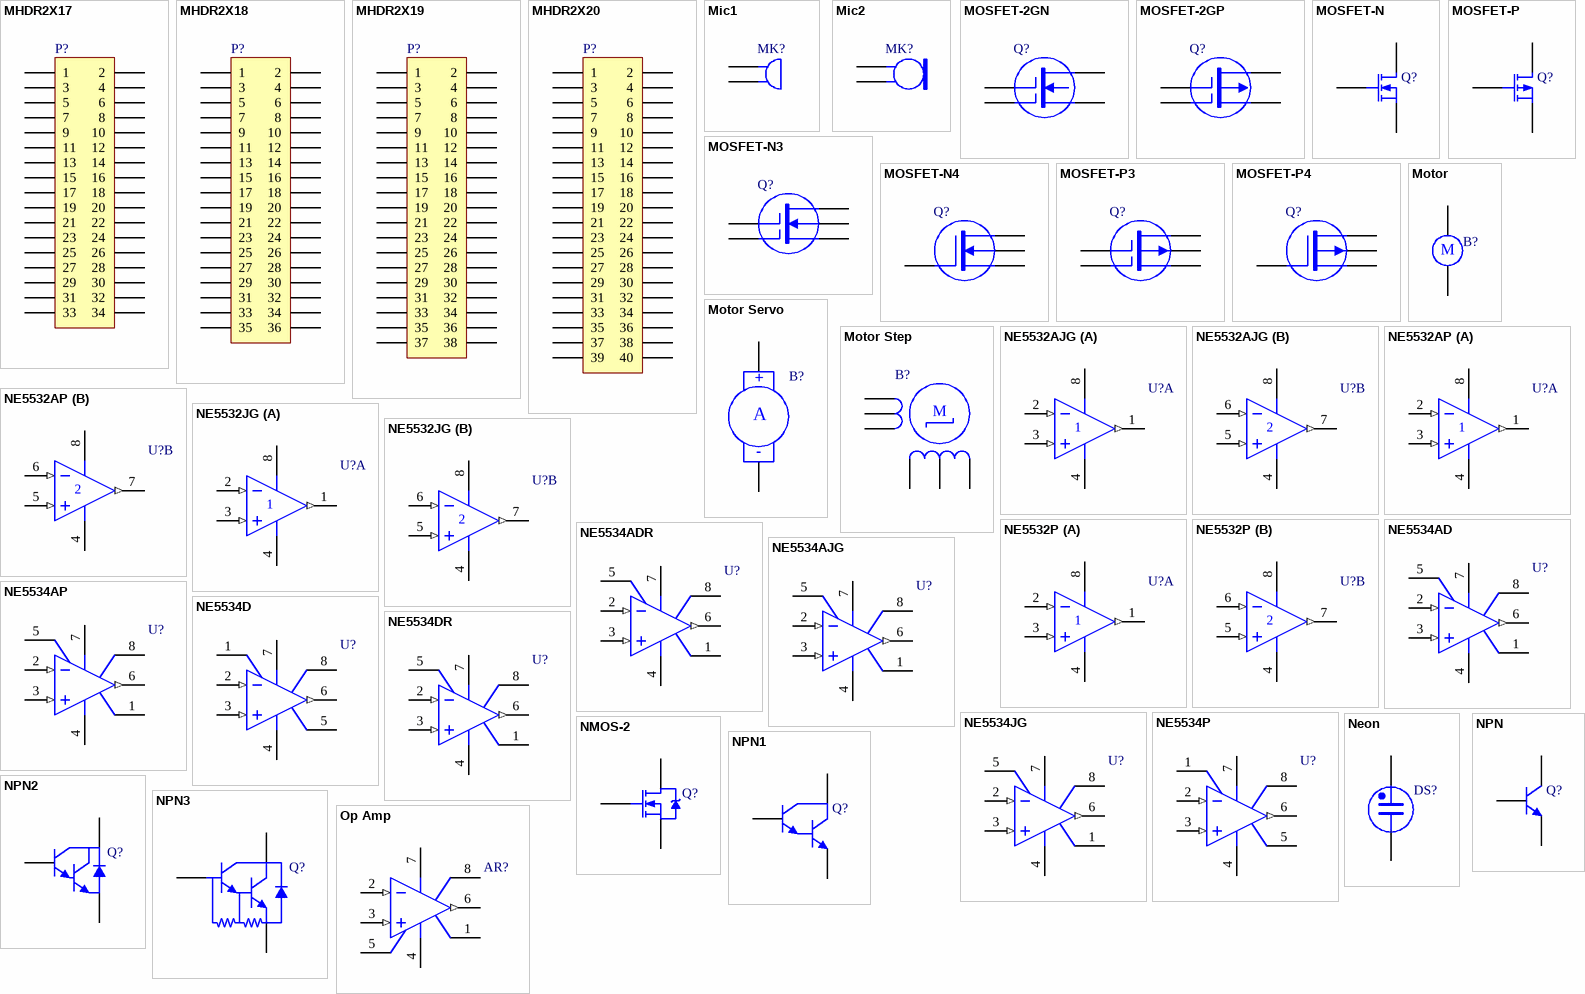
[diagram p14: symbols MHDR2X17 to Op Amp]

## MHDR2X17
designator P?
Header, 17-Pin, Dual row
footprint MHDR2X17 (Connector; Header; 17x2 Position)
signal-integrity model Connector
pins: 1, 2, 3, 4, 5, 6, 7, 8, 9, 10, 11, 12, 13, 14, 15, 16, 17, 18, 19, 20, 21, 22, 23, 24, 25, 26, 27, 28, 29, 30, 31, 32, 33, 34

## MHDR2X18
designator P?
Header, 18-Pin, Dual row
footprint MHDR2X18 (Connector; Header; 18x2 Position)
signal-integrity model Connector
pins: 1, 2, 3, 4, 5, 6, 7, 8, 9, 10, 11, 12, 13, 14, 15, 16, 17, 18, 19, 20, 21, 22, 23, 24, 25, 26, 27, 28, 29, 30, 31, 32, 33, 34, 35, 36

## MHDR2X19
designator P?
Header, 19-Pin, Dual row
footprint MHDR2X19 (Connector; Header; 19x2 Position)
signal-integrity model Connector
pins: 1, 2, 3, 4, 5, 6, 7, 8, 9, 10, 11, 12, 13, 14, 15, 16, 17, 18, 19, 20, 21, 22, 23, 24, 25, 26, 27, 28, 29, 30, 31, 32, 33, 34, 35, 36, 37, 38

## MHDR2X20
designator P?
Header, 20-Pin, Dual row
footprint MHDR2X20 (Connector; Header; 20x2 Position)
signal-integrity model Connector
pins: 1, 2, 3, 4, 5, 6, 7, 8, 9, 10, 11, 12, 13, 14, 15, 16, 17, 18, 19, 20, 21, 22, 23, 24, 25, 26, 27, 28, 29, 30, 31, 32, 33, 34, 35, 36, 37, 38, 39, 40

## Mic1
designator MK?
Microphone
footprint PIN2 (Microphone; 2 Leads)
pins: 1, 2

## Mic2
designator MK?
Microphone
footprint PIN2 (Microphone; 2 Leads)
pins: 1, 2

## MOSFET-2GN
designator Q?
Two-Gate, N-Channel MOSFET
footprint T05A (TO, Thru-Hole, Vertical, Heatsink Mounted; 5 In-Line Leads; Pitch 1.70 mm)
pins: 1 G1, 2 G2, 3 D, 4 S

## MOSFET-2GP
designator Q?
Two-Gate, P-Channel MOSFET
footprint SOT-143_N (SOT143, 4-Leads, Body 2.9x1.3mm, Pitch 1.9mm, Lead Span 2.5mm, IPC Medium Density)
footprint SOT-143_L (SOT143, 4-Leads, Body 2.9x1.3mm, Pitch 1.9mm, Lead Span 2.5mm, IPC High Density)
footprint SOT-143_M (SOT143, 4-Leads, Body 2.9x1.3mm, Pitch 1.9mm, Lead Span 2.5mm, IPC Low Density)
pins: 1 G1, 2 G2, 3 D, 4 S

## MOSFET-N
designator Q?
N-Channel MOSFET
footprint E3 (TO, Flat Index; 3 In-Line, Axial Leads; Body Dia. 4.6mm; Lead Dia. 0.5 mm (max))
simulation model NMOS (MOSFET-N)
pins: 1 D, 2 G, 3 S

## MOSFET-N3
designator Q?
Two-Gate, N-Channel MOSFET, Externally Terminated Substrate
footprint T05A (TO, Thru-Hole, Vertical, Heatsink Mounted; 5 In-Line Leads; Pitch 1.70 mm)
pins: 1 G1, 2 G2, 3 D, 4 U, 5 S

## MOSFET-N4
designator Q?
N-Channel MOSFET, Externally Terminated Substrate
footprint SOT-343_N (SOT343, 4-Leads, Body 2x1.3 mm, Pitch 1.3mm, Lead Span 2.1mm, IPC Medium Density)
footprint SOT-343_L (SOT343, 4-Leads, Body 2x1.3 mm, Pitch 1.3mm, Lead Span 2.1mm, IPC High Density)
footprint SOT-343_M (SOT343, 4-Leads, Body 2x1.3 mm, Pitch 1.3mm, Lead Span 2.1mm, IPC Low Density)
simulation model NMOS (MOSFET-N)
pins: 1 G, 2 D, 3 U, 4 S

## MOSFET-P
designator Q?
P-Channel MOSFET
footprint E3 (TO, Flat Index; 3 In-Line, Axial Leads; Body Dia. 4.6mm; Lead Dia. 0.5 mm (max))
simulation model PMOS (MOSFET-P)
pins: 1 D, 2 G, 3 S

## MOSFET-P3
designator Q?
Two-Gate, P-Channel MOSFET, Externally Terminated Substrate
footprint T05B (TO, Thru-Hole, Vertical, Heatsink Mounted; 5 Bent Staggered Leads; Pitch 1.7 mm)
pins: 1 G1, 2 G2, 3 D, 4 U, 5 S

## MOSFET-P4
designator Q?
P-Channel MOSFET, Externally Terminated Substrate
footprint SOT223_N (SOT223, 4-Leads, Body 6.5x3.5mm, Pitch 2.3mm, Lead Span 7mm, IPC Medium Density)
footprint SOT223_L (SOT223, 4-Leads, Body 6.5x3.5mm, Pitch 2.3mm, Lead Span 7mm, IPC High Density)
footprint SOT223_M (SOT223, 4-Leads, Body 6.5x3.5mm, Pitch 2.3mm, Lead Span 7mm, IPC Low Density)
simulation model PMOS (MOSFET-P)
pins: 1 G, 2 D, 3 U, 4 S

## Motor
designator B?
Motor, General Kind
footprint RB5-10.5 (Capacitor (Radial); 2 Leads)
pins: 1, 2

## Motor Servo
designator B?
Servo Motor
footprint RAD-0.4 (Radial Cap, Thru-Hole; 2 Leads; 0.4 in Pin Spacing)
pins: 1 +, 2 -

## Motor Step
designator B?
Motor Stepper
footprint DIP-6 (DIP; 6 Leads; Row Spacing 7.62 mm; Pitch 2.54 mm)
pins: 1, 2, 3, 4, 5, 6

## NE5532AJG
designator U?
Dual Low-Noise Operational Amplifier
footprint JG008 (DIP; 8 Leads; Row Spacing 7.62 mm; Pitch 2.54 mm)
3D model JG008 (DIP; 8 Leads; Row Spacing 7.62 mm; Pitch 2.54 mm)
pins on every part: 4 V- (power), 8 V+ (power)
part A pins: 1 OUT (out), 2 IN- (in), 3 IN+ (in)
part B pins: 5 IN+ (in), 6 IN- (in), 7 OUT (out)

## NE5532AP
designator U?
Dual Low-Noise Operational Amplifier
footprint P008 (DIP; 8 Leads; Row Spacing 7.62 mm; Pitch 2.54 mm)
3D model P008 (DIP; 8 Leads; Row Spacing 7.62 mm; Pitch 2.54 mm)
pins on every part: 4 V- (power), 8 V+ (power)
part A pins: 1 OUT (out), 2 IN- (in), 3 IN+ (in)
part B pins: 5 IN+ (in), 6 IN- (in), 7 OUT (out)

## NE5532JG
designator U?
Dual Low-Noise Operational Amplifier
footprint JG008 (DIP; 8 Leads; Row Spacing 7.62 mm; Pitch 2.54 mm)
3D model JG008 (DIP; 8 Leads; Row Spacing 7.62 mm; Pitch 2.54 mm)
pins on every part: 4 V- (power), 8 V+ (power)
part A pins: 1 OUT (out), 2 IN- (in), 3 IN+ (in)
part B pins: 5 IN+ (in), 6 IN- (in), 7 OUT (out)

## NE5532P
designator U?
Dual Low-Noise Operational Amplifier
footprint P008 (DIP; 8 Leads; Row Spacing 7.62 mm; Pitch 2.54 mm)
3D model P008 (DIP; 8 Leads; Row Spacing 7.62 mm; Pitch 2.54 mm)
pins on every part: 4 V- (power), 8 V+ (power)
part A pins: 1 OUT (out), 2 IN- (in), 3 IN+ (in)
part B pins: 5 IN+ (in), 6 IN- (in), 7 OUT (out)

## NE5534AD
designator U?
Low-Noise Operational Amplifier
footprint D014_N (SOIC, 14-Leads, Body 8.7x3.9mm, Pitch 1.27mm, IPC Medium Density)
footprint D014_L (SOIC, 14-Leads, Body 8.7x3.9mm, Pitch 1.27mm, IPC High Density)
footprint D014_M (SOIC, 14-Leads, Body 8.7x3.9mm, Pitch 1.27mm, IPC Low Density)
3D model D014 (14-Pin Small Outline Integrated Circuit 1.27 mm Pitch)
pins: 1 BAL, 2 IN- (in), 3 IN+ (in), 4 V- (power), 5 CMPEN, 6 OUT (out), 7 V+ (power), 8 COMP/BAL

## NE5534ADR
designator U?
Low-Noise Operational Amplifier
footprint D014_N (SOIC, 14-Leads, Body 8.7x3.9mm, Pitch 1.27mm, IPC Medium Density)
footprint D014_L (SOIC, 14-Leads, Body 8.7x3.9mm, Pitch 1.27mm, IPC High Density)
footprint D014_M (SOIC, 14-Leads, Body 8.7x3.9mm, Pitch 1.27mm, IPC Low Density)
3D model D014 (14-Pin Small Outline Integrated Circuit 1.27 mm Pitch)
pins: 1 BAL, 2 IN- (in), 3 IN+ (in), 4 V- (power), 5 CMPEN, 6 OUT (out), 7 V+ (power), 8 COMP/BAL

## NE5534AJG
designator U?
Low-Noise Operational Amplifier; ComponentAvailability: Obsolete
footprint JG008 (DIP; 8 Leads; Row Spacing 7.62 mm; Pitch 2.54 mm)
3D model JG008 (DIP; 8 Leads; Row Spacing 7.62 mm; Pitch 2.54 mm)
pins: 1 BAL, 2 IN- (in), 3 IN+ (in), 4 V- (power), 5 CMPEN, 6 OUT (out), 7 V+ (power), 8 COMP/BAL

## NE5534AP
designator U?
Low-Noise Operational Amplifier
footprint P008 (DIP; 8 Leads; Row Spacing 7.62 mm; Pitch 2.54 mm)
3D model P008 (DIP; 8 Leads; Row Spacing 7.62 mm; Pitch 2.54 mm)
pins: 1 BAL, 2 IN- (in), 3 IN+ (in), 4 V- (power), 5 CMPEN, 6 OUT (out), 7 V+ (power), 8 COMP/BAL

## NE5534D
designator U?
Low-Noise Operational Amplifier
footprint D008_L (SOIC, 8-Leads, Body 4.9x3.9mm, Pitch 1.27mm, IPC High Density)
footprint D008_M (SOIC, 8-Leads, Body 4.9x3.9mm, Pitch 1.27mm, IPC Low Density)
footprint D008_M (SOIC, 8-Leads, Body 4.9x3.9mm, Pitch 1.27mm, IPC Low Density)
3D model D008 (8-Pin Small Outline Integrated Circuit 1.27 mm Pitch)
simulation model NE5534 (SUBCKT)
pins: 1 BAL, 2 IN- (in), 3 IN+ (in), 4 V- (power), 5 CMPEN, 6 OUT (out), 7 V+ (power), 8 CMPEN/BAL

## NE5534DR
designator U?
Low-Noise Operational Amplifier
footprint D014_N (SOIC, 14-Leads, Body 8.7x3.9mm, Pitch 1.27mm, IPC Medium Density)
footprint D014_L (SOIC, 14-Leads, Body 8.7x3.9mm, Pitch 1.27mm, IPC High Density)
footprint D014_M (SOIC, 14-Leads, Body 8.7x3.9mm, Pitch 1.27mm, IPC Low Density)
3D model D014 (14-Pin Small Outline Integrated Circuit 1.27 mm Pitch)
pins: 1 BAL, 2 IN- (in), 3 IN+ (in), 4 V- (power), 5 CMPEN, 6 OUT (out), 7 V+ (power), 8 COMP/BAL

## NE5534JG
designator U?
Low-Noise Operational Amplifier
footprint JG008 (DIP; 8 Leads; Row Spacing 7.62 mm; Pitch 2.54 mm)
3D model JG008 (DIP; 8 Leads; Row Spacing 7.62 mm; Pitch 2.54 mm)
pins: 1 BAL, 2 IN- (in), 3 IN+ (in), 4 V- (power), 5 CMPEN, 6 OUT (out), 7 V+ (power), 8 COMP/BAL

## NE5534P
designator U?
Low-Noise Operational Amplifier
footprint P008 (DIP; 8 Leads; Row Spacing 7.62 mm; Pitch 2.54 mm)
3D model P008 (DIP; 8 Leads; Row Spacing 7.62 mm; Pitch 2.54 mm)
simulation model NE5534 (SUBCKT)
pins: 1 BAL, 2 IN- (in), 3 IN+ (in), 4 V- (power), 5 CMPEN, 6 OUT (out), 7 V+ (power), 8 CMPEN/BAL

## Neon
designator DS?
Neon Bulb
footprint PIN2 (Neon Bulb; 2 Leads)
pins: 1, 2

## NMOS-2
designator Q?
N-Channel Power MOSFET; Note: Pin 2 is electrically connected to pin 4.
footprint TO-220AB (TO, Thru-Hole, Vertical, Heatsink Mounted; 3 In-Line Leads; Pitch 2.54 mm)
simulation model IRF1010 (Spice Subcircuit)
pins: 1 G, 2 D, 3 S

## NPN
designator Q?
NPN Bipolar Transistor
footprint TO-92 (TO, Flat Index; 3 In-Line, Axial Leads; Body Dia. 4.6mm; Leads 0.41 x 0.39 mm (max))
simulation model NPN
signal-integrity model NPN
pins: 1 C, 2 B, 3 E

## NPN1
designator Q?
NPN Darlington Bipolar Transistor
footprint TO-92 (TO, Flat Index; 3 In-Line, Axial Leads; Body Dia. 4.6mm; Leads 0.41 x 0.39 mm (max))
simulation model NPN1 (Spice Subcircuit)
signal-integrity model NPN
pins: 1 C, 2 B, 3 E

## NPN2
designator Q?
NPN Darlington Bipolar Transistor
footprint TO-226-AE (TO, Flat Index; 3 In-Line, Axial Leads; Body Dia. 4.8mm; Leads 0.55 x 0.51 mm (max))
simulation model NPN2 (Spice Subcircuit)
signal-integrity model NPN
pins: 1 C, 2 B, 3 E

## NPN3
designator Q?
NPN Darlington Bipolar Transistor
footprint TO-237-AA (TO, Flat Index; 3 In-Line, Axial Leads; Body Dia. 4.8mm; Lead Dia. 0.56 mm (max))
simulation model NPN3 (Spice Subcircuit)
signal-integrity model NPN
pins: 1 C, 2 B, 3 E

## Op Amp
designator AR?
FET Operational Amplifier
footprint H-08A (Can; 8 Leads; Pin Circle Dia. 5.08 mm; Lead Dia. 0.53 mm (max))
simulation model AD645A (Spice Subcircuit)
pins: 1 OS NUL, 2 IN- (in), 3 IN+ (in), 4 V- (power), 5 OS NUL, 6 OUT (out), 7 V+ (power), 8 TAB

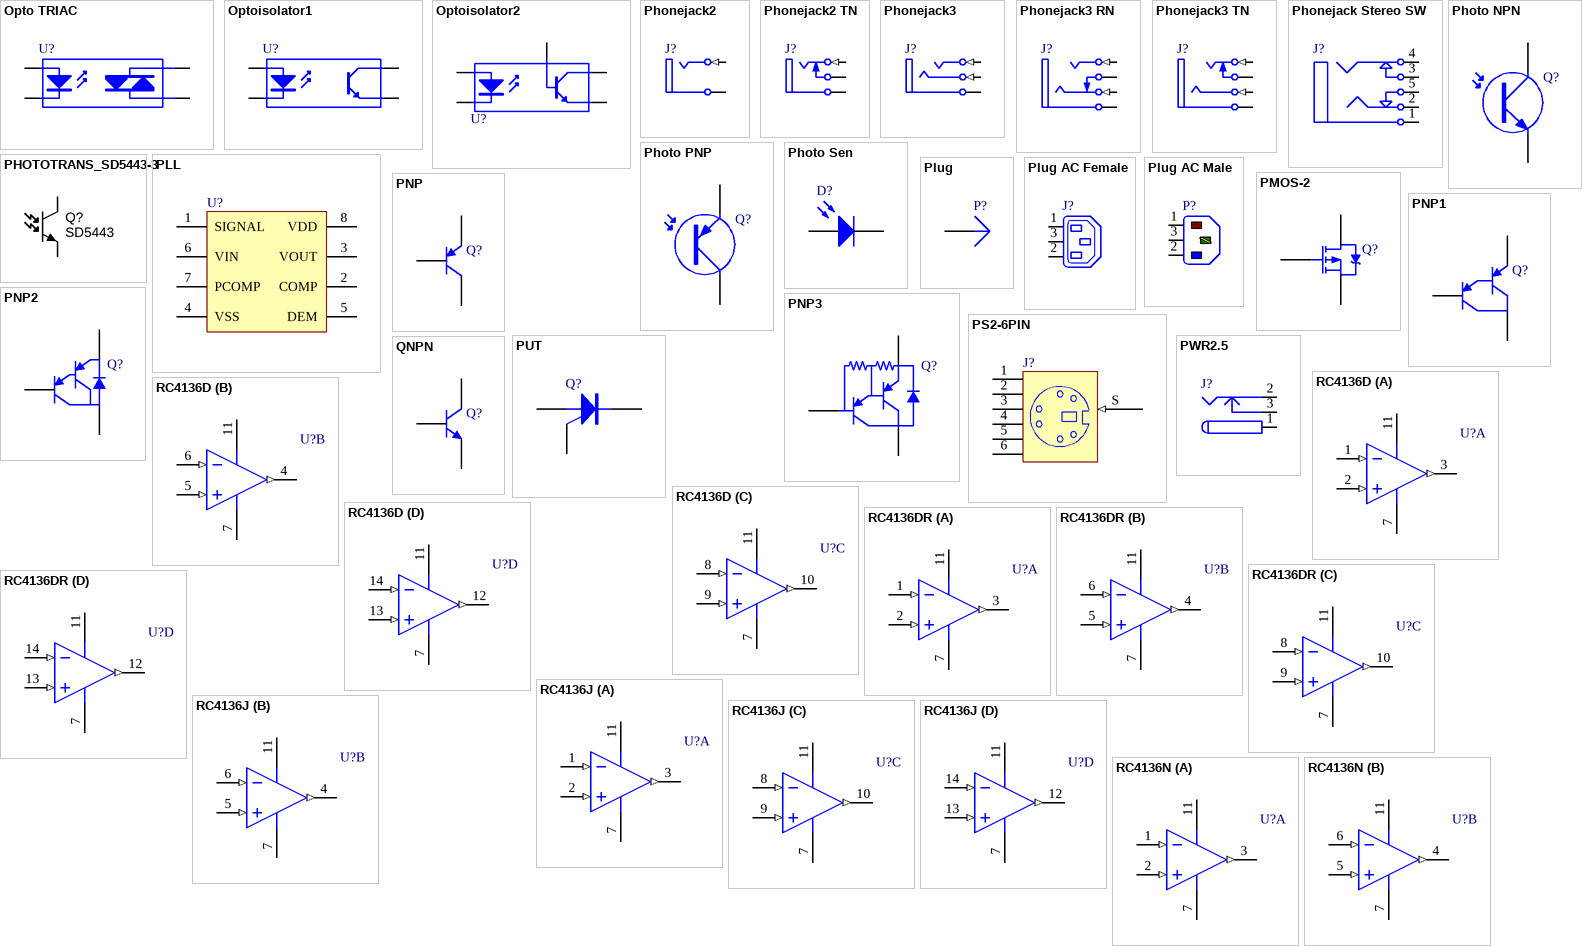
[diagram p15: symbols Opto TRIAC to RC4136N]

## Opto TRIAC
designator U?
Opto-Triac
footprint NPSIP4A (SIP; 4 Leads; Body 10 x 11.5 x 7.5 mm (typ); Pitch 2.54 mm)
pins: 1 A, 2 K, 3 A/K, 4 A/K

## Optoisolator1
designator U?
4-Pin Phototransistor Optocoupler
footprint DIP-4 (DIP; 4 Leads; Row Spacing 7.62 mm; Pitch 2.54 mm)
pins: 1 A "Anode", 2 K "Cathode", 3 E "Emitter", 4 C "Collector"

## Optoisolator2
designator U?
5 Pin Mini Flat Pack Optocoupler
footprint SOP5(6) (Small Outline; 6 Leads (1 Absent); Body Width 4.4 mm; Pitch 1.27 mm)
simulation model OPTOISO (Spice Subcircuit)
pins: 1 A "Anode", 3 K "Cathode", 4 E "Emitter", 5 C "Collector", 6 B "Base"

## Phonejack2
designator J?
Jack Socket, 1/4" [6.5mm], Thru-Hole, Vertical, 2-Conductor Open Circuit; PackageDocument: 2003; PCB_Layout: Complies with manufacturer's recommendation.; DrillAndSlotSize: Corresponds to nominal value.
footprint JACK/6-V2 (Connector; Jack Socket, 1/4" [6.5mm], Thru-Hole, 2 Position, Vertical, Body 15.7 x 15.7 x 31 mm (WxTxH))
signal-integrity model JACK Socket
pins: 1 T (in) "Tip", 5 S (power) "Sleeve (Ground)"

## Phonejack2 TN
designator J?
Jack Socket, 1/4" [6.5mm], Thru-Hole, Vertical, 2-Conductor with Tip closed; PackageDocument: 2003; PCB_Layout: Complies with manufacturer's recommendation.; DrillAndSlotSize: Corresponds to nominal value.
footprint JACK/6-V3A (Connector; Jack Socket, 1/4" [6.5mm], Thru-Hole, 3 Position, Vertical, Body 15.7 x 15.7 x 31 mm (WxTxH))
signal-integrity model JACK Socket
pins: 1 T (in) "Tip", 2 TN "Tip Normal (Break Contact)", 5 S (power) "Sleeve (Ground)"

## Phonejack3
designator J?
Jack Socket, 1/4" [6.5mm], Thru-Hole, Vertical, 3-Conductor Open Circuit (Non-Normalling); PackageDocument: 2003; PCB_Layout: Complies with manufacturer's recommendation.; DrillAndSlotSize: Corresponds to nominal value.
footprint JACK/6-V3 (Connector; Jack Socket, 1/4" [6.5mm], Thru-Hole, 3 Position, Vertical, Body 15.7 x 15.7 x 31 mm (WxTxH))
signal-integrity model JACK Socket
pins: 1 T (in) "Tip/Left Channel/(+)", 3 R (in) "Ring/Right Channel/(-)", 5 S (power) "Sleeve (Ground)"

## Phonejack3 RN
designator J?
Jack Socket, 1/4" [6.5mm], Thru-Hole, Vertical, 3-Conductor with Tip open & Ring closed; PackageDocument: 2003; PCB_Layout: Complies with manufacturer's recommendation.; DrillAndSlotSize: Corresponds to nominal value.
footprint JACK/6-V4A (Connector; Jack Socket, 1/4" [6.5mm], Thru-Hole, 4 Position, Vertical, Body 15.7 x 15.7 x 31 mm (WxTxH))
signal-integrity model JACK Socket
pins: 1 T (in) "Tip/Left Channel/(+)", 3 R (in) "Ring/Right Channel/(-)", 4 RN "Ring Normal (Break Contact)", 5 S (power) "Sleeve (Ground)"

## Phonejack3 TN
designator J?
Jack Socket, 1/4" [6.5mm], Thru-Hole, Vertical, 3-Conductor with Tip closed & Ring open; PackageDocument: 2003; PCB_Layout: Complies with manufacturer's recommendation.; DrillAndSlotSize: Corresponds to nominal value.
footprint JACK/6-V4 (Connector; Jack Socket, 1/4" [6.5mm], Thru-Hole, 4 Position, Vertical, Body 15.7 x 15.7 x 31 mm (WxTxH))
signal-integrity model JACK Socket
pins: 1 T (in) "Tip/Left Channel/(+)", 2 TN "Tip Normal (Break Contact)", 3 R (in) "Ring/Right Channel/(-)", 5 S (power) "Sleeve (Ground)"

## Phonejack Stereo SW
designator J?
3-Conductor Jack with 2 break contacts (normals) and 2 auxiliary make contacts
footprint ST-3150-5N (Connector; Stereo Jack, 3.5mm, 5 Position)
signal-integrity model Connector
pins: 1, 1A, 1B, 2, 2A, 2B, 3, 3A, 3B, 4, 4A, 4B, 5, 5A, 5B

## Photo NPN
designator Q?
NPN Phototransistor
footprint TO-220_A (TO, Thru-Hole, Vertical, Heatsink Mounted; 3 In-Line Leads (1 Absent); Pitch 2.54 mm)
pins: 1 C, 3 E

## Photo PNP
designator Q?
PNP Phototransistor
footprint TO-220_A (TO, Thru-Hole, Vertical, Heatsink Mounted; 3 In-Line Leads (1 Absent); Pitch 2.54 mm)
pins: 1 C, 3 E

## Photo Sen
designator D?
Photosensitive Diode
footprint PIN2 (Photosensitive Diode; 2 Leads)
pins: 1 A, 2 K

## PHOTOTRANS_SD5443-3
designator Q?, comment SD5443
Transistor Photo 30V 8mA 150mW TO-46; Manufacturer 1: Honeywell Sensing and Control; Manufacturer Part Number 1: SD5443-003; Ratings: 30V; 8mA; Material: Si
footprint TO-18 phototransistor (Can; 3 Leads; Pin Circle Dia. 2.54 mm; Lead Dia. 0.48 mm (max))
pins: 1 E, 3 C

## PLL
designator U?
Generic Phase Locked Loop
footprint DB008_N (SOP, 8-Leads, Body 3x5.3mm, Pitch 0.65mm, IPC Medium Density)
footprint DB008_L (SOP, 8-Leads, Body 3x5.3mm, Pitch 0.65mm, IPC High Density)
footprint DB008_M (SOP, 8-Leads, Body 3x5.3mm, Pitch 0.65mm, IPC Low Density)
simulation model PLLx (Spice Subcircuit)
pins: 1 SIGNAL, 2 COMP, 3 VOUT, 4 VSS, 5 DEM, 6 VIN, 7 PCOMP, 8 VDD

## Plug
designator P?
Plug
footprint PIN1 (Connector; Plug)
signal-integrity model Connector
pins: 1

## Plug AC Female
designator J?
IEC Mains Power Outlet, EN60 320-2-2 F Class I, PC Flange Rear Mount, Chassis Socket; PackageDocument: ver.80, 15-Sep-2003; MaximumRating: 10A, 250V a.c. (UL & CSA 15A, 250V a.c.); MountingFixtures: Not drawn on schematic symbol.; PCB_Layout: Complies with manufacturer's recommendation.; DrillSize: Corresponds to nominal value.
footprint IEC7-2H3 (Mains Power Outlet, IEC60 320-2-2 F, PC Flange Rear Mount)
pins: 1 L (power) "Live (Active)", 2 N (power) "Neutral", 3 E (power) "Earth (Ground)"

## Plug AC Male
designator P?
IEC Mains Power Inlet, EN60 320-1 C14 Class I Cold Condition, PC Flange Rear Mount, Chassis Plug; PackageDocument: ver.80, 15-Sep-2003; MaximumRating: 10A, 250V a.c. (UL & CSA 15A, 250V a.c.); MountingFixtures: Not drawn on schematic symbol.; PCB_Layout: Complies with manufacturer's recommendation.; DrillSize: Corresponds to nominal value.; Note: IEC Color Scheme employed for L, N and E.
footprint IEC9.14-2H3 (Mains Power Inlet, IEC60 320-1 C14, PC Flange Rear Mount)
pins: 1 L (power) "Live (Active)", 2 N (power) "Neutral", 3 E (power) "Earth (Ground)"

## PMOS-2
designator Q?
P-Channel Power MOSFET; Note: Pin 4 not drawn and electrically connected to Pin 2.
footprint TO-220AB (TO, Thru-Hole, Vertical, Heatsink Mounted; 3 In-Line Leads; Pitch 2.54 mm)
simulation model IRF9510 (Spice Subcircuit)
pins: 1 G, 2 D, 3 S

## PNP
designator Q?
PNP Bipolar Transistor
footprint SOT-23B_N (SOT23, 3-Leads, Body 2.9x1.3mm, Pitch 0.95mm, Lead Span 2.4mm, IPC Medium Density)
footprint SOT-23B_L (SOT23, 3-Leads, Body 2.9x1.3mm, Pitch 0.95mm, Lead Span 2.4mm, IPC High Density)
footprint SOT-23B_M (SOT23, 3-Leads, Body 2.9x1.3mm, Pitch 0.95mm, Lead Span 2.4mm, IPC Low Density)
simulation model PNP
signal-integrity model PNP
pins: 1 C, 2 B, 3 E

## PNP1
designator Q?
PNP Darlington Bipolar Transistor
footprint E3 (TO, Flat Index; 3 In-Line, Axial Leads; Body Dia. 4.6mm; Lead Dia. 0.5 mm (max))
simulation model PNP1 (Spice Subcircuit)
signal-integrity model PNP
pins: 1 E, 2 B, 3 C

## PNP2
designator Q?
PNP Darlington Bipolar Transistor
footprint TO-226-AE (TO, Flat Index; 3 In-Line, Axial Leads; Body Dia. 4.8mm; Leads 0.55 x 0.51 mm (max))
simulation model PNP2 (Spice Subcircuit)
signal-integrity model PNP
pins: 1 C, 2 B, 3 E

## PNP3
designator Q?
PNP Darlington Bipolar Transistor
footprint TO-226-AE (TO, Flat Index; 3 In-Line, Axial Leads; Body Dia. 4.8mm; Leads 0.55 x 0.51 mm (max))
simulation model PNP3 (Spice Subcircuit)
signal-integrity model PNP
pins: 1 C, 2 B, 3 E

## PS2-6PIN
designator J?
6 Pin Through Hole PS2 Socket (Kycon P/N)
footprint PS2-6PIN (PS2 Socket, 6 Pin, Through Hole)
signal-integrity model Connector
pins: 1, 2, 3, 4, 5, 6, S (in)

## PUT
designator Q?
Programmable Unijunction Transistor
footprint TO-52 (Can; 3 Leads; Pin Circle Dia. 2.54 mm; Lead Dia. 0.48 mm (max))
simulation model PUT (Spice Subcircuit)
pins: 1 A, 2 G, 3 K

## PWR2.5
designator J?
Low Voltage Power Supply Connector
footprint KLD-0202 (DC Power Jack, 2.5mm, KLD Series, PCB Mount)
signal-integrity model Connector
pins: 1 (power), 1A (power), 1B (power), 2 (power), 2A (power), 2B (power), 3 (power), 3A (power), 3B (power)

## QNPN
designator Q?
NPN Bipolar Transistor
footprint SOT-23B_N (SOT23, 3-Leads, Body 2.9x1.3mm, Pitch 0.95mm, Lead Span 2.4mm, IPC Medium Density)
footprint SOT-23B_L (SOT23, 3-Leads, Body 2.9x1.3mm, Pitch 0.95mm, Lead Span 2.4mm, IPC High Density)
footprint SOT-23B_M (SOT23, 3-Leads, Body 2.9x1.3mm, Pitch 0.95mm, Lead Span 2.4mm, IPC Low Density)
simulation model QNPN (NPN)
signal-integrity model NPN
pins: 1 C, 2 B, 3 E

## RC4136D
designator U?
Quad High-Performance Operational Amplifier; ComponentAvailability: Obsolete
footprint D014_N (SOIC, 14-Leads, Body 8.7x3.9mm, Pitch 1.27mm, IPC Medium Density)
footprint D014_L (SOIC, 14-Leads, Body 8.7x3.9mm, Pitch 1.27mm, IPC High Density)
footprint D014_M (SOIC, 14-Leads, Body 8.7x3.9mm, Pitch 1.27mm, IPC Low Density)
3D model D014 (14-Pin Small Outline Integrated Circuit 1.27 mm Pitch)
pins on every part: 7 V- (power), 11 V+ (power)
part A pins: 1 IN- (in), 2 IN+ (in), 3 OUT (out)
part B pins: 4 OUT (out), 5 IN+ (in), 6 IN- (in)
part C pins: 8 IN- (in), 9 IN+ (in), 10 OUT (out)
part D pins: 12 OUT (out), 13 IN+ (in), 14 IN- (in)

## RC4136DR
designator U?
Quad High-Performance Operational Amplifier; ComponentAvailability: Obsolete
footprint D014_N (SOIC, 14-Leads, Body 8.7x3.9mm, Pitch 1.27mm, IPC Medium Density)
footprint D014_L (SOIC, 14-Leads, Body 8.7x3.9mm, Pitch 1.27mm, IPC High Density)
footprint D014_M (SOIC, 14-Leads, Body 8.7x3.9mm, Pitch 1.27mm, IPC Low Density)
3D model D014 (14-Pin Small Outline Integrated Circuit 1.27 mm Pitch)
pins on every part: 7 V- (power), 11 V+ (power)
part A pins: 1 IN- (in), 2 IN+ (in), 3 OUT (out)
part B pins: 4 OUT (out), 5 IN+ (in), 6 IN- (in)
part C pins: 8 IN- (in), 9 IN+ (in), 10 OUT (out)
part D pins: 12 OUT (out), 13 IN+ (in), 14 IN- (in)

## RC4136J
designator U?
Quad High-Performance Operational Amplifier
footprint J014 (DIP; 14 Leads; Row Spacing 7.62 mm; Pitch 2.54 mm)
3D model J014 (DIP; 14 Leads; Row Spacing 7.62 mm; Pitch 2.54 mm)
pins on every part: 7 V- (power), 11 V+ (power)
part A pins: 1 IN- (in), 2 IN+ (in), 3 OUT (out)
part B pins: 4 OUT (out), 5 IN+ (in), 6 IN- (in)
part C pins: 8 IN- (in), 9 IN+ (in), 10 OUT (out)
part D pins: 12 OUT (out), 13 IN+ (in), 14 IN- (in)

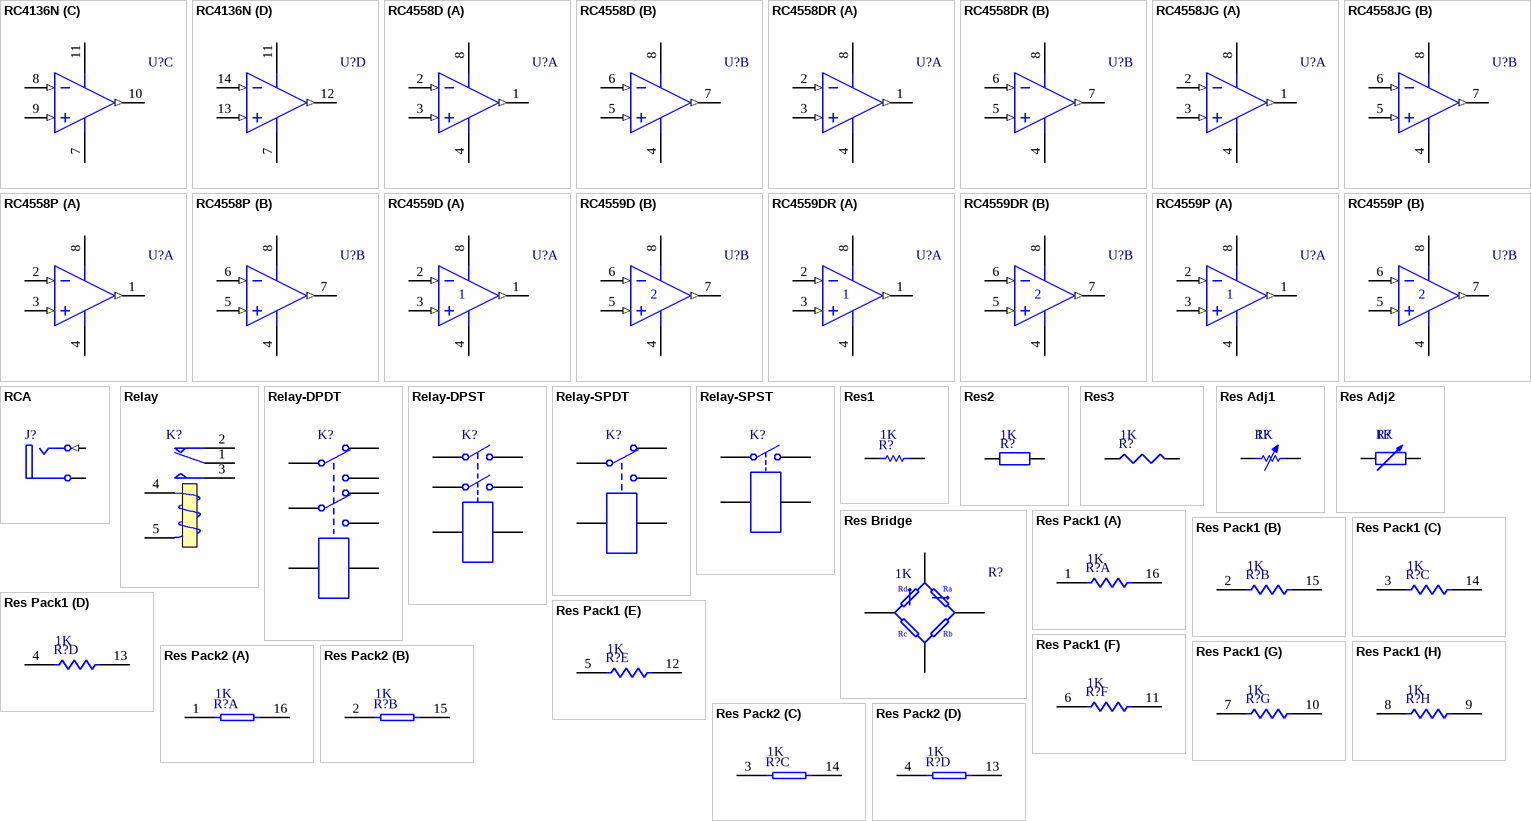
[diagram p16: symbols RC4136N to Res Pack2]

## RC4136N
designator U?
Quad High-Performance Operational Amplifier
footprint N014 (DIP; 14 Leads; Row Spacing 7.62 mm; Pitch 2.54 mm)
3D model N014 (DIP; 14 Leads; Row Spacing 7.62 mm; Pitch 2.54 mm)
pins on every part: 7 V- (power), 11 V+ (power)
part A pins: 1 IN- (in), 2 IN+ (in), 3 OUT (out)
part B pins: 4 OUT (out), 5 IN+ (in), 6 IN- (in)
part C pins: 8 IN- (in), 9 IN+ (in), 10 OUT (out)
part D pins: 12 OUT (out), 13 IN+ (in), 14 IN- (in)

## RC4558D
designator U?
Dual High-Performance Operational Amplifier
footprint D008_L (SOIC, 8-Leads, Body 4.9x3.9mm, Pitch 1.27mm, IPC High Density)
footprint D008_M (SOIC, 8-Leads, Body 4.9x3.9mm, Pitch 1.27mm, IPC Low Density)
footprint D008_M (SOIC, 8-Leads, Body 4.9x3.9mm, Pitch 1.27mm, IPC Low Density)
3D model D008 (8-Pin Small Outline Integrated Circuit 1.27 mm Pitch)
pins on every part: 4 V- (power), 8 V+ (power)
part A pins: 1 OUT (out), 2 IN- (in), 3 IN+ (in)
part B pins: 5 IN+ (in), 6 IN- (in), 7 OUT (out)

## RC4558DR
designator U?
Dual High-Performance Operational Amplifier
footprint D008_L (SOIC, 8-Leads, Body 4.9x3.9mm, Pitch 1.27mm, IPC High Density)
footprint D008_M (SOIC, 8-Leads, Body 4.9x3.9mm, Pitch 1.27mm, IPC Low Density)
footprint D008_M (SOIC, 8-Leads, Body 4.9x3.9mm, Pitch 1.27mm, IPC Low Density)
3D model D008 (8-Pin Small Outline Integrated Circuit 1.27 mm Pitch)
pins on every part: 4 V- (power), 8 V+ (power)
part A pins: 1 OUT (out), 2 IN- (in), 3 IN+ (in)
part B pins: 5 IN+ (in), 6 IN- (in), 7 OUT (out)

## RC4558JG
designator U?
Dual High-Performance Operational Amplifier
footprint JG008 (DIP; 8 Leads; Row Spacing 7.62 mm; Pitch 2.54 mm)
3D model JG008 (DIP; 8 Leads; Row Spacing 7.62 mm; Pitch 2.54 mm)
pins on every part: 4 V- (power), 8 V+ (power)
part A pins: 1 OUT (out), 2 IN- (in), 3 IN+ (in)
part B pins: 5 IN+ (in), 6 IN- (in), 7 OUT (out)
